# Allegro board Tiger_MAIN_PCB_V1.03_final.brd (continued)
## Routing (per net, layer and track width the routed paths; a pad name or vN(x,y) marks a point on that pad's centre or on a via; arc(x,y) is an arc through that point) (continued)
+V3.3S_AUDIO: length 57.4
  TOP w0.508: v2(20.97,15.87) 20.97,19.72 21.49,20.24 21.49,23.75 v2(20.65,24.59) 19.71,24.59 18.64,25.66 13.33,25.66 10.41,22.74 v2(10.41,21.98) 11.08,21.31 11.08,17.88 10.29,17.09 7.09,17.09 5.77,18.41 5.77,22.44 8.25,24.91 8.25,26.57 v2(7.15,27.67)
  LAY3 w0.305: v2(20.97,15.87) 20.39,15.29 20.39,13.18 17.49,10.28 v2(16.95,10.28)
  BOTTOM w0.203: U16.36 9.67,21.16 C435.2 9.35,21.48 C434.2 10.12,22.27 v2(10.41,21.98)
  BOTTOM w0.305: FB13.1 v2(20.65,24.59) ; R346.1 16.74,10.28 v2(16.95,10.28)
  BOTTOM w0.406: v2(20.97,15.87) 20.97,15.87 R360.2
+V3.3S_MSATA:
  vias: v1(77.27,52.7) v1(78.03,35.61)
+V3P3_BIOS_SPI: length 18.3
  TOP w0.203: R707.1 175.26,51.08 175.02,50.85 175.02,48.48 U42.8 175.26,43.83 174.57,43.14 174.57,40.6 174.09,40.11 174.09,37.75 174.32,37.51 R708.1 174.75,37.05 v2(174.82,36.98) ; R709.1 v2(177.27,36.98)
  BOTTOM w0.203: v2(174.82,36.98) v2(177.27,36.98)
+V3P3A: length 438.1
  TOP w0.203: v2(184.54,48.56) R115.1 R114.1 R113.1 ; 176.66,64.85 176.66,65.68 R632.1 176.22,66.12 R732.2 ; 176.66,64.85 176.61,64.91 175.13,64.91 174.36,64.14 R131.2 ; 176.66,64.85 177.11,64.4 179.96,64.4 R112.2 ; R94.1 v2(187.32,49.75) ; R112.2 R105.2 ; R112.2 181.29,64.41 182.7,64.41 183.65,65.35 R77.1 ; R733.2 183,59.38 v2(182.83,59.21) ; 179.04,73.4 176.58,73.4 176.4,73.57 ; 179.04,73.4 179.04,71.59 179.37,71.26 179.6,71.26 R82.1 180.13,70.68 180.46,70.35 v2(180.46,70.02) 179.78,69.35 R83.1 179.03,68.79 178.16,68.79 177.97,68.98 177.97,69.36 177.81,69.53 176.5,69.53 176.18,69.85 176.18,71.29 176.52,71.63 R56.2 177.65,71.63 R55.2 ; 179.04,73.4 R61.1 R62.1 180.61,73.45 R90.2 181.35,74.48 182.41,75.55 R14.1 183.16,74.98 183.47,74.67 R140.2 ; R113.1 183.86,50.75 R253.1 ; R113.1 R37.1 ; v2(188.56,50.07) 188.55,50.08 R93.2 ; 187.66,82.69 188.25,82.1 R38.1 ; 187.66,82.69 187.65,82.69 187.65,83.09 ; 187.66,82.69 187.25,82.69 ; R134.1 180.39,68.38 v2(180.39,68.33) 179.97,67.91 R57.1 179.98,67.7 R58.1 ; R87.2 v2(179.07,39.09) ; v2(182.93,50.11) 182.9,50.13 R75.1 ; v2(190.11,48.09) R92.1
  TOP w0.254: R523.1 R524.2 244.79,74.82 244.45,75.15 241.64,75.15 241.24,74.76 C282.1 v2(241.8,73.87) U5.1 ; v2(175.54,54.66) 175.54,54.22 R86.1 ; R769.2 v2(163.94,40.93)
  TOP w0.305: LED2.1 103.78,8.47 103.27,8.97 101.25,8.97 99.43,10.79 99.43,14.97 100.89,16.43 100.89,20.65 108.88,28.63 112.22,28.63 v2(113.3,29.71) ; R65.1 R64.1 R63.1 R68.1 188.2,83.63 v2(186.52,81.95) ; v1(168.37,55.01) 167.66,54.3 U6.5 167.52,54.3 R663.2 166.84,53.28 166.39,52.83 166.39,49.5 165.84,48.95 R767.2 165.84,47.74 v2(165.85,47.72) ; v2(173.25,74.93) 173.58,74.93 174.93,73.57 176.4,73.57 ; v2(173.36,64.14) R131.2
  TOP w0.508: v2(173.33,38.69) 173.33,40.37 172.46,41.24 D1.P
  LAY3 w0.203: v2(241.93,42.59) 245.33,39.19 245.33,27.4 248.75,23.99 248.75,16.1 241.23,8.58 169.11,8.58 164.28,13.4 v2(164.28,24.09) ; v2(182.83,59.21) 179.11,59.21 178.21,60.1 176.68,60.1 175.11,58.54 175.11,55.09 v2(175.54,54.66) ; v2(182.93,50.11) 182.49,49.67 182.49,48.78 182.71,48.56 v2(184.54,48.56)
  LAY3 w0.305: v2(180.39,68.33) 180.46,68.4 v2(180.46,70.02) ; v2(173.25,74.93) 173.25,78.25 176.83,81.83 186.4,81.83 v2(186.52,81.95) ; v2(113.3,29.71) 111.57,31.44 111.57,46.88
  LAY3 w0.762: v1(168.56,24.7) 168.56,36.89 167.7,37.75 v2(167.7,38.5) 169.14,39.95 169.14,46.71 168.39,47.46 168.39,49.13 168.83,49.56 168.83,51.11 168.48,51.46 168.48,54.9 v1(168.37,55.01)
  LAY4 w0.305: v2(173.36,64.14) 172.6,63.38 171.54,63.38 170.8,64.12 ; 170.8,64.12 167.75,61.07 167.75,59.86 167.48,59.6 v2(167.04,59.6) ; 170.8,64.12 174.2,67.52 179.58,67.52 v2(180.39,68.33)
  LAY6 w0.203: v2(165.85,47.72) 168.17,47.72 168.64,48.19 170.66,48.19 171.15,47.7 173.09,47.7 173.95,48.56 v2(184.54,48.56) 185.96,49.98 187.09,49.98 v2(187.32,49.75) 188.24,49.75 v2(188.56,50.07) ; v2(173.33,38.69) 178.68,38.69 v2(179.07,39.09)
  LAY6 w0.254: v2(241.93,42.59) 241.8,42.72 v2(241.8,73.87)
  LAY6 w0.508: v2(173.33,38.69) 172.47,39.56 168.75,39.56 v2(167.7,38.5)
  BOTTOM w0.203: v2(175.54,54.66) 174.78,54.66 173.82,53.69 ; v2(190.11,48.09) 190.11,48.18 188.56,49.73 v2(188.56,50.07) ; R544.2 v2(241.93,42.59)
  BOTTOM w0.254: R377.2 138.01,38.75
  BOTTOM w0.305: v2(163.94,40.93) 164.75,40.11 171.91,40.11 v2(173.33,38.69)
  BOTTOM w0.508: v2(167.04,59.6) 167.68,59.6 167.86,59.77
  vias: v1(21.68,61.11) v1(21.68,59.84) v1(22.45,61.11) v1(22.45,59.84) v1(23.21,61.11) v1(23.21,59.84) v1(23.97,61.11) v1(23.97,59.84) v1(111.07,47.38) v1(111.09,48.24) v1(138.87,40.1) v1(162.07,24.81) v1(162.07,24.05)
+V3P3A_DSW: length 393.1
  TOP w0.203: R9.1 190.95,46.86 v2(190.66,46.57)
  TOP w0.508: v1(36.97,54.66) 36.97,55.65 42.19,60.88 43.72,60.88 44.43,61.59 44.43,64.18 45.42,65.17 R23.1 44.62,66.57 44.62,69.05 45.41,69.84 R829.1 45.41,77.04 v2(48.39,80.02)
  LAY3 w0.305: v2(190.66,46.57) 189.6,46.57 189.15,46.11 184.92,46.11 v2(182.42,43.61) ; v2(171.77,43.32) 170.91,44.18 170.91,47.89 170.8,48.01 v2(170.8,52)
  LAY3 w0.508: v2(157.45,53.77) 156.71,54.5 156.71,67.65 155.85,68.51 155.85,70.79 v2(156.44,71.38)
  LAY3 w0.762: v1(148.38,89.89) 146.14,89.89 v1(143.07,92.96)
  LAY3 w1.016: v1(143.07,92.96) 142.69,93.34 106.27,93.34 83.32,70.39 83.32,61.53 76,54.21 74.47,54.21 72.87,52.61 v1(72.87,44.56)
  LAY6 w0.305: v2(171.77,43.32) 172.06,43.61 v2(182.42,43.61) ; v2(157.45,53.77) 159.09,52.13 162.31,52.13 163.23,53.04 169.76,53.04 v2(170.8,52)
  LAY6 w0.508: v2(48.39,80.02) 71.94,80.02 76.65,75.31 v2(85.32,75.31) 87.8,75.31 92.54,70.57 119.66,70.57 123,67.23 142.04,67.23 143.79,68.98 151.55,68.98 153.95,71.38 v2(156.44,71.38)
  LAY6 w1.016: 35.6,50.5 56.85,50.5 62.79,44.56 v1(72.87,44.56)
  BOTTOM w0.203: v2(170.8,52) 170.8,50.4 171.34,49.86 R54.1 172.88,50.8 R19.1 172.91,50.84 R11.1 ; v2(12.22,64.71) 12.06,64.88 12.06,70.24 12.26,70.44 R72.1 ; R18.1 R10.1 191.16,48.12 190.96,47.93 190.96,46.87 v2(190.66,46.57)
  BOTTOM w0.305: R71.1 16.67,61.51 v1(16.13,62.05) ; R132.2 182.42,43.6 v2(182.42,43.61) ; v2(157.45,53.77) 157.95,53.26 R774.1
  BOTTOM w0.508: v2(85.32,75.31) 85.32,77.61 86.03,78.31 D30.P ; v2(14.7,65.87) 14.69,65.88 R776.2
  BOTTOM w0.762: v1(148.38,89.89) 150.22,88.04 150.22,79.78 149.65,79.21 FB45.2
  vias: v1(13.86,62.42) v1(14.62,62.42) v1(15.39,62.42) v1(36.11,54.66)
+V3P3A_RTC: length 156.9
  TOP w0.178: U1.BB14 194.51,54.29 v2(194.52,54.27)
  TOP w0.254: U1.AK19 v2(197.87,61.42)
  LAY3 w0.305: v2(182.26,42.07) 177.6,42.07 175.84,43.84 175.84,45.74 176.71,46.61 176.75,46.61 ; v2(174.3,47.91) 175.62,47.91 176.75,46.79 176.75,46.61 ; 176.75,46.61 v2(177.17,46.61)
  LAY3 w0.508: v2(85.97,56.43) 85.97,68.16 89.4,71.59 v2(89.4,74.84)
  LAY6 w0.508: v2(85.97,56.43) 86.53,56.99 91.56,56.99 92.28,56.27 95.81,56.27 97.86,54.22 100.31,54.22 101.3,55.22 113.28,55.22 117.96,50.53 140.01,50.53 145.34,45.19 156.86,45.19 157.73,46.06 158.6,46.06 159.73,47.19 163.87,47.19 164.34,46.72 173.11,46.72 v2(174.3,47.91)
  BOTTOM w0.152: v2(174.3,47.91) 174.3,49.09 173.72,49.68 R12.2
  BOTTOM w0.203: v2(177.17,46.61) R6.2 R7.2
  BOTTOM w0.254: 193.34,49.65 193.15,49.46 193.15,43.77 190.84,41.46 182.87,41.46 v2(182.26,42.07)
  BOTTOM w0.508: v2(89.4,74.84) 89.4,75.34 88.93,75.81 D31.N D30.N
+V3P3A_SIP: length 129.5
  TOP w0.254: U1.AG15 194.71,63.56 v2(194.97,63.21) ; U1.AK17 v2(196.05,61.42) ; U1.Y16 v2(195.62,66.57) ; v2(194.22,61.42) 194.27,61.48 U1.AK15 194.97,62.27 v2(194.97,62.38) ; U1.V19 v2(197.58,67.4) ; U1.AJ21 v2(198.88,63.21) ; U1.T16 v2(195.62,68.24)
  TOP w0.305: v2(194.97,62.38) 195.3,62.71 U1.AJ16 ; C225.2 178.42,61.74 v2(178.4,61.72)
  LAY3 w0.152: 187.62,62.2 188.47,63.05 194.79,63.05 194.95,63.21 v2(194.97,63.21)
  LAY3 w0.254: v2(178.4,61.72) 178.89,62.2 187.62,62.2
  LAY4 w0.254: v2(172.09,64.11) 172.09,64.61 174.34,66.86 181.72,66.86 182.22,67.36 194.73,67.36 v2(195.62,68.24) ; v2(195.62,66.57) 195.62,66.28 195.36,66.02 194.35,66.02 193.66,65.34 178.1,65.34 177.09,64.33 174.67,64.33 172.57,62.23 v2(172.09,62.23)
  BOTTOM w0.254: v2(172.09,64.11) C229.2 170.7,63.31 R119.2 ; R127.2 191.38,36.59 197.76,42.97 197.76,51.37 C245.2 ; 169.41,62.07 169.65,62.31 170.93,62.31 C226.2 171.64,61.79 v2(172.09,62.23)
  BOTTOM w0.508: 177.12,41.66 177.12,39.75 181.18,35.69 184.84,35.69 185.21,36.06 R127.2 ; 168.52,51.72 173.18,47.06 175.4,47.06 175.4,43.38 ; R119.2 170.7,63.07 169.39,63.07
  vias: v2(184.09,55.43) v2(184.65,55.43)
+V5_AVDD: length 4.4
  BOTTOM w0.203: 10.91,16.83 11.24,17.16 U16.26
  BOTTOM w0.406: 9.06,14.82 10.42,14.82 10.91,15.31 10.91,16.83
+V5_PVDD: length 12.4
  BOTTOM w0.203: 16.52,23.4 16.52,22.77 15.93,22.19 U16.46 ; U16.41 13.93,22.58 13.09,23.42 13.09,23.64
  BOTTOM w0.508: 16.52,23.4 16.27,23.64 16.27,24.68 16.15,24.81 C449.2 16.15,25.7 C450.1 13.52,26.36 ; C448.1 13.09,25.94 C447.2 12.83,24.94 12.83,23.9 13.09,23.64
+V5A: length 504.4
  TOP w0.203: R563.1 41.1,22.45 41.61,21.94 41.61,21.08 41.25,20.73 41.25,19.52 ; R558.1 60.96,12.18
  TOP w0.254: v2(170.98,79.26) 171.01,79.29 C807.2 171.16,79.82 171.95,80.62 U56.4 ; U67.4 167.91,61.09 C689.2 167.25,61.09 166.88,61.46 v2(166.88,62.72) ; C758.2 160.66,46.48 160.66,46.26 161.04,45.88 U41.10
  TOP w0.305: v2(156.66,43.71) 156.66,42.63 158.36,40.93 162.62,40.93 163.72,39.82 165.08,39.82 ; v2(156.66,43.71) D26.P 153.08,43.71 152.79,44 v1(151.85,44) ; v2(156.66,43.71) 157.19,44.24 157.19,45.44 158.04,46.29 159.65,46.29 C758.2 ; 165.08,39.82 165.07,39.82 v2(165.07,38.03) 167.02,36.08 173.25,36.08 v2(173.39,36.22) ; 165.08,39.82 165.59,39.82 168.76,43 168.76,43.88 R763.2 ; v2(240.14,83.42) 240.28,83.28 246.96,83.28 250.53,86.85 v2(250.53,90)
  TOP w0.508: 18.31,70.44 18.31,72.14 v2(16.62,73.83)
  LAY3 w0.203: v2(165.07,38.03) 165.07,27.87 165.85,27.08 165.85,18.08 173.7,10.23 176.66,10.23 177.68,9.22 240.97,9.22 248.07,16.32 248.07,23.34 244.7,26.72 244.7,35.8 241.59,38.9 v2(241.59,39.95)
  LAY3 w0.305: v2(156.66,43.71) 157.12,44.17 157.12,48.45 158.04,49.37 158.04,55.24 157.31,55.98 157.31,62.81 v2(157.36,62.86) ; v2(173.39,36.22) 173.39,30.63 v2(174.46,29.56) 174.56,29.56 v2(176.26,27.86)
  LAY3 w0.406: v2(204.78,97.48) 205.17,97.87 207.07,97.87 208.39,99.2 218.08,99.2 219.12,100.24 237.17,100.24 239.98,103.06 247.08,103.06 250.53,99.61 v2(250.53,90)
  LAY3 w0.508: v2(204.78,97.48) 184.83,97.48 184.3,96.95 181.17,96.95 180.15,97.97 176.21,97.97 175.87,97.64 170.89,97.64 169.18,95.93 v2(169.18,95.71)
  LAY3 w1.016: v1(151.85,44) 150.89,44.95 143.88,44.95 132.38,56.46 v1(124.06,56.46)
  LAY6 w0.305: v2(166.88,62.72) 166.58,63.03 162.16,63.03 161.57,63.61 157.79,63.61 157.36,63.18 v2(157.36,62.86) ; v2(241.59,39.95) 240.88,40.66 v2(240.88,42.11) 240.88,45.58 239.32,47.14 238.36,47.14 v2(236.96,48.54) 236.96,51.37 241.13,55.54 241.13,74.14 239.5,75.78 239.5,82.79 v2(240.14,83.42)
  LAY6 w0.406: v2(250.53,90) 250.32,90.2 243.76,90.2 243.24,89.68 236.24,89.68 235.1,90.82 v2(235.1,91.2)
  BOTTOM w0.152: v2(236.96,48.54) 237.32,48.89 R813.2
  BOTTOM w0.203: U103.34 238.57,85.05 C716.2 239.08,84.23 239.88,83.42 v2(240.14,83.42) ; R270.2 v2(174.46,29.56) ; 240.7,38.17 U29.9 ; U71.14 16.36,73.34 16.62,73.59 v2(16.62,73.83)
  BOTTOM w0.254: U45.6 176.76,95.47 C321.1 ; v2(204.78,97.48) 204.78,96.73 205.4,96.11 C323.1 207.76,96.32 U50.6 ; v2(170.98,79.26) 170.98,80.98 165.88,86.08 163.72,86.08 ; U59.4 157.01,61.48 C702.2 157.01,62.51 v2(157.36,62.86)
  BOTTOM w0.305: v2(176.26,27.86) C512.1 176.66,26.94 U21.6 ; 165.88,86.08 165.88,93.92 167.67,95.71 v2(169.18,95.71) 170.44,94.45 175.73,94.45 C321.1 ; R553.1 v2(240.88,42.11) ; 163.72,86.08 158.74,86.08 C325.1 158.74,87.75 159.23,88.24 U54.6 ; 240.7,38.17 241.44,38.92 C696.2 ; R814.2 v1(30.26,71.93)
  BOTTOM w0.406: v2(241.59,39.95) C696.2 ; v1(29.5,71.93) 27.12,71.93 26.64,71.45 C778.1 26.64,70.99 D24.1
  BOTTOM w0.508: v2(19.56,65.59) 19.91,65.94 R782.1
  vias: v1(26.5,42.31) v1(26.88,88.3) v1(27.26,42.31) v1(27.64,88.3) v1(28.03,42.31) v1(29.5,71.17) v1(29.5,70.4) v1(30.26,71.17) v1(30.26,70.4) v1(36.64,45.79) v1(41.23,16.09) v1(61.22,11.11)
+V5S: length 331.6
  TOP w0.152: R625.2 191.29,40.57 190.48,39.76 188.63,39.76 188.31,39.44 188.31,35.92 178.24,25.85 171.07,25.85 v2(170.64,26.28)
  TOP w0.203: R608.1 v2(161.4,12.89)
  TOP w0.406: R535.2 137.36,55.72 v2(136.44,56.64) 136.44,57.48 137.38,58.42 144.9,58.42 145.77,57.55 C564.1 U35.6
  TOP w0.508: R817.2 36.39,75.28 33.95,75.28 33.11,76.12 33.11,77.07 ; FB21.2 162.85,22.5 163.34,22.98 v2(164.81,22.98)
  LAY3 w0.203: v2(164.81,22.98) 164.81,13.94 v2(165.86,12.89) 169.87,8.89 241.1,8.89 248.38,16.16 248.38,23.69 245.03,27.05 245.03,35.91 242.14,38.79 242.14,40.05 238.32,43.87 v2(238.32,44.6)
  LAY3 w0.406: v2(136.44,56.64) 135.57,57.51 122.87,57.51 v1(121.9,56.55)
  LAY3 w0.508: v1(121.9,56.55) 121.9,56 122.38,55.52 131.72,55.52 148.96,38.27 153.36,38.27 165.04,26.59 165.04,23.21 v2(164.81,22.98)
  LAY3 w1.016: v1(5.23,14.42) 4.22,15.43 4.22,27.43 8.5,31.71 v1(12.41,31.71)
  LAY6 w0.203: v2(164.81,22.98) 165.71,22.98 169.02,26.28 v2(170.64,26.28) ; v1(30.32,80.34) v2(30.32,86.97)
  LAY6 w0.508: v2(43.11,67.36) 39.59,67.36 35.06,71.88 34.03,71.88 32.91,73.01 32.91,78 v1(31.84,79.07)
  BOTTOM w0.203: R152.1 v2(238.32,44.6) ; R342.1 26.52,89.28 28.62,89.28 30.32,87.58 v2(30.32,86.97) ; v2(161.4,12.89) v2(165.86,12.89)
  BOTTOM w0.254: R399.1 R404.1 R400.1 v2(43.11,67.36)
  vias: v1(12.41,30.95) v1(23.64,50.89) v1(23.64,49.84) v1(24.4,50.89) v1(24.4,49.84) v1(29.56,80.34) v1(29.56,79.07) v1(30.32,79.07) v1(31.08,80.34) v1(31.08,79.07) v1(31.84,80.34)
+V5S_HDD:
  vias: v1(98.41,54.95) v1(99.3,54.97)
+V15A: length 6.8
  TOP w0.406: R70.1 v2(23.21,63.46)
  BOTTOM w0.305: v2(23.21,63.46) 24.28,62.4 25.13,62.4 R809.1 25.14,61.26 R806.1
  BOTTOM w0.406: v2(23.21,63.46) 22.99,63.46 D25.2 22.37,63.51 C776.1
+VCCCORE: length 148.2
  TOP w0.102: 211.11,72.01 211.13,72.04 U1.K43
  TOP w0.127: 205.65,72.22 U1.K33 ; U1.K33 205.93,72.5 ; U1.K33 205.65,72.78 ; 207.02,61.94 U1.AL37 ; U1.AL37 207.02,61.39 ; U1.AL37 206.74,61.66 ; U1.AL37 207.3,61.66 ; U1.J37 208.21,72.97 ; U1.J37 207.65,72.97 ; U1.J37 207.93,72.69 ; U1.J37 207.93,73.24 ; U1.AK33 205.65,62.41 ; U1.AK33 205.65,61.85 ; U1.AK33 205.37,62.13 ; U1.AK37 207.2,62.13 ; U1.AK37 207.48,61.85 ; U1.AK37 207.48,62.41 ; U1.AM33 205.93,61.19 ; U1.AM33 205.65,60.91 ; U1.AM33 205.37,61.19 ; U1.AM33 205.65,61.47 ; 208.85,61.94 U1.AL40 ; U1.AL40 209.13,61.66 ; U1.AL40 208.57,61.66 ; U1.AL40 208.85,61.39 ; U1.G38 v2(207.93,73.68) U1.G37 ; U1.G37 207.48,73.15 ; U1.G37 207.76,73.43 ; U1.K40 209.58,72.5 ; U1.K40 209.3,72.22 ; U1.K40 209.3,72.78 ; 209.3,61.85 U1.AK40 ; U1.AK40 209.3,62.41 ; U1.AK40 209.03,62.13 ; U1.AK40 209.58,62.13 ; 207.48,60.91 U1.AM37 ; U1.AM37 207.2,61.19 ; U1.AM37 207.76,61.19 ; U1.AM37 207.48,61.47 ; U1.G33 v2(206.1,73.68) U1.G35 ; U1.G33 205.65,73.15 ; U1.G33 205.88,73.18 ; U1.AM38 208.11,61.19 ; U1.AM38 208.39,60.91 ; U1.AM38 208.67,61.19 ; U1.AM38 208.39,61.47 ; U1.AK38 208.67,62.13 ; U1.AK38 208.39,61.85 ; U1.AK38 208.39,62.41 ; U1.J33 205.82,72.97 ; U1.J33 206.38,72.97 ; U1.J33 206.1,72.69 ; U1.J33 206.1,73.24 ; U1.AL33 204.91,61.66 ; U1.AL33 205.47,61.66 ; U1.AL33 205.19,61.39 ; U1.AL33 205.19,61.94 ; U1.K37 207.48,72.78 ; U1.K37 207.48,72.22 ; U1.K37 207.76,72.5 ; 206.56,61.47 U1.AM35 ; U1.AM35 206.28,61.19 ; U1.AM35 206.56,60.91 ; U1.AM35 206.84,61.19 ; v2(204.28,73.68) U1.G32 204.73,73.15 ; U1.K38 208.11,72.5 ; U1.K38 208.39,72.22 ; U1.K38 208.39,72.78 ; U1.J30 204.28,73.24 ; U1.J30 204.28,72.69 ; U1.J30 204.55,72.97 ; 204.73,61.5 U1.AM32 204.73,60.89 ; U1.J40 209.48,72.97 ; U1.J40 209.76,72.69 ; U1.J40 210.04,72.97 ; U1.J40 209.76,73.24 ; U1.K35 206.28,72.5 ; U1.K35 206.56,72.78 ; U1.K35 206.56,72.22 ; 206.57,73.03 U1.G35 ; U1.G35 206.28,73.43 ; U1.G35 206.56,73.15 ; U1.K42 210.22,72.22 ; U1.K42 210.22,72.78 ; U1.K42 v2(209.76,72.27) ; U1.AK35 206.56,62.41 ; U1.AK35 206.56,61.85 ; U1.AK35 206.84,62.13
  TOP w0.152: 208.39,73.07 U1.G38 ; 209.3,73.09 U1.G40 209.51,73.43 v2(209.76,73.68) 210.02,73.43 U1.G42 210.22,73.1
  TOP w0.203: U1.G30 v2(204.28,73.68) ; U1.A39 v2(209.2,78.04) ; U1.A34 v2(206.72,78.04) ; U1.A30 v2(204.24,78.14) ; U1.A44 v2(211.68,78.04)
  TOP w0.305: v2(187.84,86.1) 187.83,86.08 R815.2 ; C34.2 204.75,78.94 204.24,78.43 v2(204.24,78.14) ; C32.2 206.1,78.27 206.34,78.04 v2(206.72,78.04) ; v2(209.2,78.04) 208.58,78.66 C33.2
  LAY6 w0.254: v2(197,100.33) 197.11,100.44 209.94,100.44 211.16,101.66 232.56,101.66 234.31,103.41 242.27,103.41 244.11,101.57 244.66,101.57 v2(245.19,102.1)
  LAY6 w0.305: v2(241.33,100.12) 240.04,100.12 237.42,102.74 v2(235.76,102.74)
  BOTTOM w0.203: C304.1 243.16,96.92 C303.2 ; C304.1 243.16,96.43 243.42,96.18 243.42,95.68 R217.1 ; C304.1 243.89,97.65 C307.1 244.07,98.14 R244.1 ; 210.54,64.52 210.75,64.31 210.75,63.69 210.53,63.47 C62.1 C50.1 ; R214.2 243.47,100.4 R215.1 245.19,101.3 v2(245.19,102.1)
  BOTTOM w0.254: R244.1 245.28,99.42 R215.1
  BOTTOM w0.305: v2(241.33,100.12) 241.65,100.44 241.65,101.2 R681.2 ; v2(235.76,102.74) 226.03,102.74 224.41,101.13 224.41,97.16 223.33,96.08 223.33,93.12 222.32,92.11 219.94,92.11 219.18,91.35 216.88,91.35 214.4,88.87 214.4,87.87
  vias: v1(192.41,93.51) v1(193.19,93.51) v1(193.87,90.92) v1(194.5,93.51) v1(194.65,90.92) v1(195.24,93.51) v1(195.96,93.51) v1(195.91,90.88) v1(195.96,90.05) v1(196.75,93.51) v1(196.7,90.88) v1(197.79,90.83) v1(197.8,90.01) v1(198.07,93.51) v1(198.58,90.83) v1(198.51,88.79) v1(198.59,90.01) v1(198.81,93.51) v1(199.26,88.79) v1(199.33,89.98) v1(199.56,93.51) v1(199.89,86.41) v1(200.34,93.51) v1(202.82,90.72) v1(203.38,90.21) v1(203.96,89.73) v2(192.49,85.59) v2(194.3,85.58) v2(200.26,85.2) v2(200.26,84.63) v2(200.23,82.97) v2(200.78,82.44) v2(202.29,91.65) v2(202.96,82.13) v2(203.01,79.32) v2(203.92,82.2) v2(204.28,72.27) v2(204.59,68.41) v2(204.59,67.33) v2(204.59,66.26) v2(205.19,62.36) v2(205.39,71.57) v2(205.65,63.07) v2(206.1,72.27) v2(206.1,60.8) v2(206.39,71.56) v2(206.56,63.07) v2(207.02,62.36) v2(207.02,60.8) v2(207.16,68.37) v2(207.16,67.29) v2(207.16,66.22) v2(207.48,71.56) v2(207.48,63.07) v2(207.71,68.37) v2(207.71,67.29) v2(207.71,66.22) v2(207.93,72.27) v2(207.93,60.8) v2(208.26,71.56) v2(208.39,63.07) v2(208.85,62.36) v2(209.43,71.56) v2(210.12,71.56) v2(210.35,80.03) v2(210.35,78.13) v2(210.35,68.39) v2(210.35,67.32) v2(210.35,66.24)
+VCCDSW_1P0: length 2.4
  TOP w0.152: 185.79,61.35 U1.AL1
  TOP w0.305: 185.79,61.35 185.77,61.37 C228.1
+VCCGT: length 116.9
  TOP w0.076: 217.99,73.27 U1.J55 217.99,72.66 ; U1.K60 220.28,72.19 ; U1.K60 220.58,72.5 ; U1.K60 219.97,72.5 ; U1.K60 220.28,72.81 ; 214.03,72.97 U1.J48 ; U1.J48 214.33,73.27 ; U1.J48 214.33,72.66 ; 213.57,72.5 U1.K48 ; U1.K48 213.88,72.81 ; U1.K48 213.88,72.19 ; U1.K48 214.18,72.5 ; 217.23,72.5 U1.K55 ; U1.K55 217.53,72.19 ; U1.K55 217.53,72.81 ; U1.K55 217.84,72.5 ; 218.91,72.66 U1.J56 218.91,73.27 ; 219.67,72.5 U1.K58 ; U1.K58 219.36,72.81 ; U1.K58 219.36,72.19 ; U1.K58 219.06,72.5 ; 216.31,72.5 U1.K53 ; U1.K53 216.62,72.81 ; U1.K53 216.62,72.19 ; U1.K53 216.93,72.5 ; U1.J53 217.38,72.97 ; U1.J53 217.08,72.66 ; U1.J53 216.77,72.97 ; U1.L67 224.25,71.31 ; U1.L67 224.56,71.61 ; U1.L67 224.86,71.31 ; 213.11,72.97 U1.J46 213.42,72.66 ; U1.K50 214.79,72.19 ; U1.K50 214.49,72.5 ; U1.K50 215.1,72.5 ; U1.K50 214.79,72.81 ; 215.55,72.97 U1.J50 215.25,72.66 ; 225.51,65.82 U1.AC68 225.21,66.13 ; 226.16,71.31 U1.L69 225.55,71.31 ; U1.K52 215.71,72.81 ; U1.K52 215.4,72.5 ; U1.K52 216.01,72.5 ; U1.K52 215.71,72.19 ; 211.9,72.97 U1.J43 211.93,73.12 ; U1.J45 212.51,73.27 ; U1.J45 212.51,72.66 ; U1.J45 212.81,72.97 ; U1.K56 218.45,72.19 ; U1.K56 218.75,72.5 ; U1.K56 218.14,72.5 ; U1.K56 218.45,72.81 ; 219.82,72.66 U1.J58 219.55,72.7 ; 227.46,71.31 U1.L71 226.85,71.31 ; 216.16,73.27 U1.J52 216.16,72.66 ; 224.21,71.31 U1.L66 223.6,71.31 ; U1.J60 220.73,73.27 ; U1.L65 223.25,71.61
  TOP w0.102: 224.52,69.75 224.56,69.72 U1.R67 ; U1.R68 225.21,69.17 ; U1.R68 224.9,69.48 ; U1.R68 225.21,69.7 225.25,69.74 ; U1.R68 225.51,69.48 ; U1.W66 223.91,67.9 223.88,67.93 ; U1.W66 223.91,67.34 ; U1.W66 223.6,67.65 ; U1.W66 224.21,67.65 ; U1.M62 221.49,70.54 ; U1.M62 221.79,70.85 ; U1.M62 221.18,70.85 ; U1.M62 221.49,71.15 ; U1.AA64 222.6,66.48 222.58,66.45 ; U1.AA64 222.6,67.04 ; U1.AA64 222.3,66.73 ; 222.26,70.39 U1.N63 ; U1.N63 221.65,70.39 ; U1.N63 221.95,70.7 ; U1.N63 221.95,70.09 ; U1.L64 222.6,71.61 ; U1.L64 222.3,71.31 ; U1.L64 222.91,71.31 ; U1.L64 222.6,71 ; U1.L63 221.95,71 ; U1.L63 222.26,71.31 ; U1.L63 221.95,71.61 ; U1.L63 221.65,71.31 ; 221.65,66.73 U1.AA63 ; U1.AA63 221.95,67.04 ; U1.AA63 221.95,66.43 ; U1.AA63 222.26,66.73 ; 223.56,68.56 U1.U65 ; U1.U65 222.95,68.56 ; U1.U65 223.25,68.26 ; U1.U65 223.25,68.87 ; 224.54,66.45 224.55,66.46 224.55,66.73 U1.AA67 ; U1.W64 222.6,67.34 ; U1.W64 222.3,67.65 ; U1.W64 222.6,67.9 222.63,67.93 ; U1.W64 222.91,67.65 ; v2(224.23,66.28) U1.AA67 ; U1.AA67 224.86,66.73 ; U1.AA67 224.25,66.73 ; U1.AA67 224.56,67.04 ; U1.N70 226.51,70.09 ; U1.N70 226.51,70.7 ; U1.N70 226.2,70.39 ; U1.N70 226.81,70.39 ; U1.AA69 225.86,66.43 ; U1.AA69 225.55,66.73 ; U1.AA69 225.86,67.04 ; U1.AA69 226.16,66.73 ; 222.26,69.48 U1.R63 ; U1.R63 221.95,69.17 ; U1.R63 221.95,69.78 ; U1.R63 221.65,69.48 ; U1.AC69 225.86,66.13 ; U1.AC69 225.55,65.82 ; U1.AC69 226.16,65.82 ; 225.51,71.31 U1.L68 ; U1.L68 224.9,71.31 ; U1.L68 225.21,71.61 ; U1.L68 225.21,71 ; U1.AC70 226.51,66.13 ; U1.AC70 226.2,65.82 ; U1.AC70 U1.AC71 ; U1.AC70 226.51,65.59 226.6,65.5 ; 222.57,70.12 222.6,70.16 U1.N64 ; 226.53,67.93 226.51,67.9 U1.W70 ; 222.3,69.48 U1.R64 ; U1.R64 222.6,69.71 222.57,69.75 ; U1.R64 222.91,69.48 ; U1.R64 222.6,69.17 ; 225.51,67.65 U1.W68 ; U1.W68 225.21,67.34 ; U1.W68 225.21,67.95 ; U1.W68 224.9,67.65 ; U1.U68 225.21,68.87 ; U1.U68 v2(224.88,68.11) ; U1.U68 225.21,68.26 ; U1.U68 225.51,68.56 ; U1.U68 224.9,68.56 ; U1.L62 221.49,71.46 ; U1.L62 221.18,71.76 ; U1.L62 221.79,71.76 ; U1.L62 221.49,72.07 ; U1.AC64 222.6,66.05 222.57,66.09 ; U1.AC64 U1.AC65 ; U1.AC64 222.6,65.51 ; U1.AC64 222.3,65.82 ; U1.N69 225.86,70.09 ; U1.N69 226.16,70.39 ; U1.N69 225.55,70.39 ; U1.N69 225.86,70.7 ; 224.21,65.82 U1.AC66 ; U1.AC66 223.6,65.82 ; U1.AC66 223.91,66.13 ; 221.9,67.94 221.95,67.88 U1.W63 ; U1.Y62 221.49,66.89 ; U1.Y62 221.49,67.5 ; U1.Y62 221.79,67.19 ; U1.Y62 221.18,67.19 ; 225.55,67.65 U1.W69 ; U1.W69 225.86,67.86 225.81,67.9 ; U1.W69 225.86,67.34 ; U1.W69 226.16,67.65 ; 223.56,69.48 U1.R65 ; U1.R65 222.95,69.48 ; U1.R65 223.25,69.73 223.28,69.76 ; U1.R65 223.25,69.17 ; U1.AC65 223.25,66.08 223.28,66.1 ; U1.AC65 223.56,65.82 ; 226.85,68.56 U1.U71 ; U1.U71 227.16,68.87 ; U1.U71 227.46,68.56 ; U1.U71 227.16,68.26 ; U1.L70 226.51,71.61 ; U1.L70 226.51,71 ; U1.L70 226.2,71.31 ; U1.L70 226.81,71.31 ; U1.N71 227.16,70.09 ; U1.N71 227.16,70.7 ; U1.N71 227.46,70.39 ; U1.N71 226.85,70.39 ; 227.46,66.73 U1.AA71 ; U1.AA71 227.16,66.43 ; U1.AA71 227.16,67.04 ; U1.AA71 226.85,66.73 ; U1.R69 225.86,69.78 ; U1.R69 226.16,69.48 ; U1.R69 225.55,69.48 ; U1.R69 225.86,69.17 ; U1.N66 223.91,70.09 ; U1.N66 223.91,70.7 ; U1.N66 224.21,70.39 ; U1.N66 223.6,70.39 ; 226.2,66.73 U1.AA70 ; U1.AA70 226.81,66.73 ; U1.AA70 226.51,67.04 ; U1.AA70 226.51,66.43 ; U1.AC71 227.16,65.54 ; U1.AC71 227.16,66.13 ; U1.R71 227.16,69.78 ; U1.R71 226.85,69.48 ; U1.R71 227.46,69.48 ; U1.R71 227.16,69.17 ; 224.57,67.93 224.56,67.91 U1.W67 ; U1.L66 223.91,71 ; U1.W70 226.51,67.34 ; U1.W70 226.2,67.65 ; U1.W70 226.81,67.65 ; U1.N67 224.25,70.39 ; U1.N67 224.56,70.7 ; U1.N67 224.56,70.17 224.51,70.13 ; 223.6,66.73 U1.AA66 ; U1.AA66 223.91,67.04 ; U1.AA66 224.21,66.73 ; U1.AA66 223.91,66.43 ; 221.65,67.65 U1.W63 ; U1.W63 222.26,67.65 ; U1.W63 221.95,67.34 ; 226.2,69.48 U1.R70 ; U1.R70 226.51,69.17 ; U1.R70 226.81,69.48 ; U1.R70 226.51,69.78 ; 223.56,71.31 U1.L65 ; U1.L65 222.95,71.31 ; U1.L65 223.25,71 ; 223.6,69.48 U1.R66 ; U1.R66 223.91,69.78 ; U1.R66 224.21,69.48 ; U1.R66 223.91,69.17 ; 224.56,71 U1.L67 ; U1.N64 222.3,70.39 ; U1.N64 222.6,70.7 ; 227.46,67.65 U1.W71 ; U1.W71 226.85,67.65 ; U1.W71 227.16,67.34 ; U1.W71 227.16,67.95 ; U1.R67 224.86,69.48 ; U1.R67 224.56,69.17 ; U1.R67 224.25,69.48 ; U1.L71 227.16,71 ; 224.52,66.09 224.56,66.06 U1.AC67 ; U1.T62 221.49,69.33 ; U1.T62 221.18,69.02 ; U1.T62 221.49,68.71 ; U1.T62 221.79,69.02 ; 223.25,67.34 U1.W65 ; U1.W65 223.25,67.95 ; U1.W65 223.45,67.37 v2(223.58,67.19) ; U1.W65 223.56,67.65 ; U1.W65 222.95,67.65 ; U1.L69 225.86,71 ; U1.AC67 224.25,65.82 ; U1.AC67 U1.AC68 ; 224.25,67.65 U1.W67 ; U1.W67 224.86,67.65 ; U1.W67 224.56,67.34 ; 226.83,65.76 226.83,65.53
  TOP w0.127: 227.5,71.31 U1.L71 226.85,71.31 ; 220.11,72.97 U1.J58 ; U1.J58 219.52,72.97 ; U1.J58 219.82,72.66 ; 214.67,72.97 U1.J48 ; U1.J48 214.33,72.67 ; U1.J48 214.04,72.95 ; U1.J50 215.24,72.66 ; U1.J50 214.91,72.97 ; U1.J50 215.55,72.98 ; U1.J55 217.68,72.97 ; U1.J55 217.99,72.65 ; U1.J55 218.32,72.97 ; U1.J45 212.5,72.67 ; U1.J45 212.21,72.97 ; U1.J45 212.81,72.98 ; 211.84,73.16 U1.J43 ; U1.J43 211.88,72.85 ; U1.J43 211.59,72.65 ; U1.J60 221.03,72.97 ; U1.J60 220.72,72.69 ; U1.J60 220.44,72.97 ; U1.J52 216.46,72.97 ; U1.J52 215.87,72.97 ; U1.J52 216.15,72.65 ; U1.J56 219.23,72.97 ; U1.J56 218.57,72.97 ; U1.J56 218.9,72.67 ; 226.19,71.31 U1.L69 225.51,71.3 ; 224.88,71.31 U1.L67 224.27,71.29 ; U1.J46 213.41,72.65 ; U1.J46 213.07,72.98 ; U1.J46 213.8,72.97 ; 223.16,71.63 U1.L65 ; U1.J53 217.07,72.66 ; U1.J53 216.77,72.98 ; U1.J53 217.45,72.95 ; 223.6,71.3 U1.L66 224.21,71.3
  TOP w0.203: v2(214.1,78.14) 214.16,78.09 U1.A48 ; U1.A58 v2(219.11,78.14) ; U1.A53 v2(216.63,78.14) ; U1.A62 v2(221.59,78.14) ; U1.A66 v2(224.07,78.14)
  TOP w0.305: C87.1 233.33,69.5 ; 233.31,70.1 232.79,70.1 ; 231.79,70.1 231.19,70.1 ; 231.81,69.5 231.81,70.1 ; 233.36,70.1 233.87,70.1
  LAY6 w0.305: v2(216.63,78.14) v2(214.1,78.14)
  BOTTOM w0.305: C296.1 231.58,97.49 230.51,97.49 R204.2 ; C296.1 233.26,96.98 233.62,96.62 C294.1 ; C296.1 R206.1 232.09,98.74 v2(232.07,98.75)
  BOTTOM w0.406: C294.1 C297.1 R207.2 R212.2
  vias: v1(217.29,88.77) v1(217.29,88.01) v1(217.47,90.58) v1(218.23,90.58) v1(218.58,88.77) v1(218.58,88.01) v1(219.02,90.58) v1(219.78,90.58) v1(219.8,88.77) v1(219.8,88.01) v1(220.87,91.16) v1(221.64,91.16) v1(222.42,91.16) v1(223.19,91.16) v1(225.12,91.16) v1(225.88,91.16) v1(226.67,91.16) v1(227.43,91.16) v1(228.61,90.55) v1(228.75,67.76) v1(228.83,88.74) v1(228.83,87.97) v1(229.37,90.54) v1(229.54,88.74) v1(229.54,87.97) v1(230.13,90.54) v1(230.25,88.74) v1(230.25,87.97) v1(233.47,101.53) v1(234.26,101.53) v1(235.01,101.53) v1(235.79,101.53) v2(210.71,62.54) v2(211.13,63.07) v2(211.61,72.16) v2(212.05,71.56) v2(212.05,63.07) v2(212.51,72.27) v2(212.51,62.36) v2(212.96,71.56) v2(212.96,63.07) v2(213.42,72.27) v2(213.88,71.56) v2(213.88,63.07) v2(214.33,72.27) v2(214.33,62.36) v2(214.33,60.8) v2(214.79,71.56) v2(214.79,63.07) v2(215.25,72.27) v2(215.25,60.8) v2(215.71,71.56) v2(215.71,63.07) v2(216.16,72.27) v2(216.16,62.36) v2(216.17,60.84) v2(216.62,71.56) v2(216.62,63.07) v2(217.08,72.27) v2(217.08,60.8) v2(217.53,71.56) v2(217.53,63.07) v2(217.99,72.27) v2(217.99,62.36) v2(218.45,71.56) v2(218.45,63.07) v2(218.91,72.27) v2(218.97,60.84) v2(219.24,63.07) v2(219.36,71.56) v2(219.82,72.27) v2(219.82,60.8) v2(220.28,71.56) v2(220.42,81.41) v2(220.66,72.27) v2(220.72,88.88) v2(221.07,71.28) v2(221.26,90.44) v2(221.77,90.45) v2(222.28,69.02) v2(222.28,67.19) v2(222.93,68.11) v2(223.58,70.85) v2(223.58,69.02) v2(223.85,93.29) v2(224.23,69.93) v2(224.31,93.29) v2(224.77,93.29) v2(224.88,70.85) v2(224.88,69.02) v2(224.88,67.19) v2(225.22,93.29) v2(225.53,69.93) v2(225.53,66.28) v2(226.18,70.85) v2(226.18,69.02) v2(226.18,67.19) v2(226.64,93.29) v2(226.83,69.93) v2(226.83,68.11) v2(226.83,66.28) v2(227.1,93.29) v2(227.56,93.29) v2(228.02,93.29) v2(229.15,93.29) v2(229.6,93.29) v2(229.85,91.18) v2(230.06,93.29) v2(230.38,91.19) v2(230.52,93.29) v2(230.67,70.1) v2(230.67,68.07) v2(234.17,72.64) v2(234.22,70.1) v2(234.22,68.07) v2(234.88,72.64) v2(236.28,68.48) v2(236.53,72.67) v2(236.99,68.48) v2(237.25,72.67)
+VCCPAZIO: length 33.8
  TOP w0.203: v2(189.63,40.22) 189.77,40.36 R799.1
  TOP w0.254: U1.AJ19 v2(197.58,62.38)
  TOP w0.305: R796.1 193.64,38.58 v2(189.63,38.58)
  BOTTOM w0.406: R127.1 185.21,38.09 189.14,38.09 v2(189.63,38.58) v2(189.63,40.22) 192.28,40.22 197.13,45.07 197.13,51.82 C244.2 ; R127.1 185.19,38.11 R826.1 ; R127.1 R126.1
+VCCPDSW_3P3: length 1.6
  TOP w0.254: U1.AD18 196.33,64.97 v2(196.27,64.89) U1.AD17 ; U1.AJ17 v2(196.28,62.38)
+VCCPGPPD: length 26.1
  TOP w0.254: U1.Y15 v2(194.32,66.57)
  LAY4 w0.254: v2(194.32,66.57) 194.07,66.57 193.89,66.38 188.81,66.38 188.19,65.75 177.86,65.75 176.85,64.74 174.07,64.74 v2(173.61,65.2)
  BOTTOM w0.305: R119.1 172.76,63.62 172.76,64.43 172.26,64.92 R120.1 173.57,65.15 v2(173.61,65.2)
+VCCPGPPG: length 22.5
  TOP w0.254: v2(194.32,64.89) 194.38,64.97 U1.AD15
  TOP w0.305: v2(176.45,61.69) 175.63,62.51 R121.1 R131.1
  LAY3 w0.254: v2(176.45,61.69) 177.37,62.61 187.43,62.61 189.01,64.19 193.61,64.19 v2(194.32,64.89)
+VCCSA: length 194.3
  TOP w0.127: U1.J27 202.17,72.97 ; U1.J27 202.45,72.69 ; U1.J27 202.73,72.97 ; U1.J27 202.45,73.24 ; U1.K28 202.62,72.5 ; U1.K28 202.9,72.22 ; U1.K28 202.9,72.78 ; 201.99,73.71 U1.G27 ; U1.G27 201.99,73.15 ; U1.G27 202.27,73.43 ; U1.G27 201.71,73.43 ; 200.62,72.69 U1.J23 ; U1.J23 200.62,73.24 ; U1.J23 200.34,72.97 ; U1.J23 200.9,72.97 ; U1.G28 v2(202.45,73.68) ; U1.G28 202.62,73.43 ; U1.G28 202.9,73.15 ; 199.79,73.27 U1.J22 200.05,72.97 ; U1.K27 201.99,72.78 ; U1.K27 202.27,72.5 ; U1.K27 201.99,72.22 ; 200.16,72.22 U1.K23 ; U1.K23 200.16,72.78 ; U1.K23 200.16,72.81 ; U1.K23 v2(200.62,72.27) ; U1.K25 201.08,72.78 ; U1.K25 201.08,72.22 ; U1.K25 200.8,72.5 ; 201.08,73.15 U1.G25 ; U1.G25 200.8,73.43 ; U1.G25 201.08,73.71 ; U1.G25 201.35,73.43 ; 200.44,73.26 U1.G23 ; U1.G23 200.16,73.15 ; U1.G23 v2(200.62,73.68)
  TOP w0.203: 203.82,72.94 U1.K30 203.82,72.14 ; U1.AK25 v2(201.08,63.07) ; U1.AK23 v2(200.16,63.07)
  LAY3 w0.254: v2(245.81,85.94) 245.74,86.01 244.43,86.01 243.77,85.35 239.81,85.35 238.88,86.28 237.84,86.28 235.9,88.23 235.9,88.94 234.11,90.72 232.44,90.72 230.91,92.26 210.69,92.26 210.14,92.8 206.39,92.8 205.92,92.33 204.47,92.33 203.77,93.03 201.61,93.03 200.91,92.33 192.7,92.33 191.57,91.2 169.2,91.2 v2(168.81,90.81)
  LAY3 w0.305: v2(247.76,96.63) 246.89,95.77 246.89,90.67 247.34,90.23 247.95,90.23 248.34,89.84 248.34,86.36 246.89,84.9 239.57,84.9 238.7,85.77 237.78,85.77 235.5,88.04 235.5,88.7 233.94,90.25 232.26,90.25 230.64,91.88 210.41,91.88 209.86,92.42 206.58,92.42 205.99,91.84 204.24,91.84 203.51,92.57 201.87,92.57 201.13,91.84 193.08,91.84 190.77,89.53 190.77,87.29 v2(188.71,85.23)
  BOTTOM w0.203: R223.2 C311.2 C315.2 246.31,85.44 v2(245.81,85.94) 246.3,86.42 247.45,86.42 247.86,86.01 247.86,81.52 246.26,79.92 244.81,79.92 244.53,80.19 R225.1 244.04,80.41 R228.1 243.24,81.2 R237.2
  BOTTOM w0.305: R672.2 247.79,96.66 v2(247.76,96.63) ; 188.71,85 v2(188.71,85.23)
  vias: v1(172.21,90.12) v1(172.98,90.12) v1(173.74,90.12) v1(174.47,90.12) v1(175.24,90.12) v1(176,90.12) v2(200.59,71.6) v2(201.35,71.6) v2(201.39,79.12) v2(201.53,73.68) v2(201.99,71.56) v2(202.45,72.27) v2(202.6,71.56)
+VDDQ_MEM: length 100.6
  TOP w0.152: v2(231.36,20.62) 231.37,20.62 CN1.33 ; U1.BB41 209.31,54.33
  TOP w0.178: U1.BB23 199.34,55.2 199.34,54.06 v2(199.14,53.86) ; v2(212.93,54.21) 212.97,54.28 212.97,54.63 U1.BB47 ; U1.BB32 204.36,55.04 204.35,55.01 v2(204.35,54.26)
  TOP w0.203: C173.2 213.06,53.59 212.93,53.72 v2(212.93,54.21) ; U1.BB51 v2(215.43,54.28)
  TOP w0.254: CN1.123 v2(208.86,20.62) ; CN1.178 193.11,15.44 192.8,15.75 v2(192.62,15.75) ; CN1.54 v2(226.11,15.16) ; CN1.241 177.36,20.26 177.14,20.03 v2(176.87,20.03) ; v2(201.08,15.72) 200.84,15.72 200.62,15.49 CN1.148 ; CN1.112 211.62,15.2 v2(211.61,15.2) ; CN1.163 196.86,20.81 196.67,20.62 v2(196.36,20.62) ; v2(199.65,15.73) 199.36,15.73 199.11,15.49 CN1.154 ; CN1.118 210.11,15.38 v2(210.15,15.41) ; CN1.75 220.86,19.57 220.16,18.86 v2(219.86,18.86) ; CN1.153 199.36,20.62 v2(199.36,20.62) ; C171.2 198.89,53.6 v2(199.14,53.86) ; v2(204.11,15.11) 204.11,15.11 CN1.142 ; v2(208.54,15.13) 208.62,15.06 CN1.124 ; v2(187.86,20.62) 187.87,20.62 CN1.199 ; CN1.159 197.86,20.62 v2(197.86,20.62) ; CN1.135 v2(205.86,20.62) ; C175.2 209.33,52.77 v2(209.33,53.37) 209.33,54.31 209.31,54.33 ; v2(200.86,20.62) 200.86,20.62 CN1.147 ; C174.2 204.11,53.18 204.31,53.39 204.31,54.22 v2(204.35,54.26) ; CN1.130 207.11,15.17 v2(207.12,15.17) ; v2(214.62,16.33) 214.94,16.33 215.62,15.65 CN1.96 ; CN1.160 197.62,15.06 v2(197.62,15.06) ; U1.AU35 v2(207.02,58.24) ; U1.AU28 v2(203.36,58.24) ; CN1.129 v2(207.36,20.62) ; v2(210.52,20.58) 210.36,20.74 CN1.117 ; U1.AU42 v2(210.68,58.24) ; U1.AU23 v2(200.62,58.24) ; CN1.111 v2(211.86,20.62) ; U1.AM40 209.28,61.19 v2(208.85,60.8) ; CN1.12 236.61,15.16 v2(236.61,15.16) ; CN1.141 v2(204.36,20.62) ; CN1.220 v2(182.61,15.17) ; CN1.136 v2(205.62,15.16)
  TOP w0.305: U1.AL23 v2(199.7,62.39)
  LAY3 w0.254: v2(199.7,62.39) 199.7,61.75 200.16,61.3 200.16,58.7 v2(200.62,58.24)
  LAY6 w0.305: v2(236.06,39.78) 239.58,43.31 v2(239.58,45.89)
  BOTTOM w0.203: 234.26,36.57 U29.28 ; U29.2 236.95,39.2 236.62,39.53 236.31,39.53 v2(236.06,39.78)
  BOTTOM w0.305: v2(234.99,44.68) R546.2 ; v2(239.58,45.89) U4.5 238.66,45.35 236.46,47.55 236.46,49.08 R811.2 v2(235.9,49.12) ; v2(212.93,54.21) 215.35,54.21 v2(215.43,54.28) ; v2(228.06,36.69) C698.2 231.86,36.57 234.26,36.57 ; 182.91,17.82 178.41,17.82 177.69,18.54 177.69,19.68 177.35,20.03 v2(176.87,20.03)
  vias: v1(203.59,24.52) v1(203.59,23.76) v1(204.35,24.52) v1(204.35,23.76) v1(218.45,39.14) v1(218.45,38.38) v1(218.45,37.61)
+VDDQ_VTT: length 110.6
  TOP w0.305: CN1.258 173.11,11.94
  LAY3 w0.305: v1(232.97,41) 232.99,40.99 v1(232.99,40.23)
  LAY3 w0.762: v1(232.99,40.23) 232.99,36.37 246.5,22.86 246.5,20.67 247.43,19.74 247.43,17.04 240.26,9.88 180.84,9.88 179.4,11.32 v1(177.87,11.32)
  BOTTOM w0.203: U29.31 235.52,37.77 235.16,38.13 ; U29.29 234.88,36.97
  BOTTOM w0.305: 234.88,36.97 234.78,36.97 233.83,37.93 ; 235.16,38.13 235.14,38.13 ; 235.14,38.13 234.66,38.6 ; 235.14,38.13 235.05,38.13 ; 234.71,37.79 235.05,38.13 ; 235.05,38.13 234.69,38.13
  BOTTOM w0.406: R820.2 232.61,42.07
AGND: length 187.3
  TOP w0.203: 33.95,29.72 37.1,29.72 37.63,29.2 37.63,27.53 36.8,26.7 35.87,26.7 35.39,27.17 30.97,27.17 30.04,26.24 J3.5 ; C421.2 22.62,26.44 12.57,26.44 v2(11.86,25.72) 9.73,23.6 9.73,19.86 7.98,18.11 v2(7.68,18.11) 7.26,18.52 7.26,19.78 8.49,21.01 8.49,24.27 12.01,27.78 24.29,27.78 C422.2
  TOP w0.305: R364.2 25.22,27.65 C422.2 v2(24.43,28.33) 24.43,28.93 27.25,31.75 31.92,31.75 33.95,29.72 ; C418.2 32.26,29.25 J3.2 ; B1.2 57.04,8.69 57.04,9.32 56.56,9.8 54.56,9.8 52.5,7.74 17.28,7.74 14.97,10.05 14.97,11.4 15.31,11.74 15.83,11.74 16.1,11.48 16.1,10.16 17.64,8.61 52.08,8.61 54.87,11.4 58.08,11.4 58.49,10.99 CN42.1 58.49,9.28 59.79,7.98 CN42.E2 ; v2(23.2,24.48) R363.2 C421.2 ; C419.2 v2(27.46,24.85)
  BOTTOM w0.203: U16.25 v2(11.63,16.21) 11.63,15.55 v2(11.65,15.54) ; v2(16.53,12.84) 16.71,13.02 R357.2 ; C428.2 7.87,16.84 v2(7.36,16.33) ; v2(7.68,18.11) 7.92,17.86 C432.1 ; v2(11.85,22.5) 12.4,22.5 12.73,22.17 U16.38
  BOTTOM w0.305: C414.2 v2(37.78,20.67) ; Q36.2 19.26,10.47 v2(19.26,10.75) ; C413.2 31.09,20.76 v2(31.07,20.78) ; C444.1 v2(7.06,24.69)
  BOTTOM w0.406: C441.1 12.15,25.43 v2(11.86,25.72) C442.2
  vias: v2(6.62,19.5) v2(6.63,18.91) v2(10.03,14.07)
AVDD2_AUDIO: length 44.8
  LAY3 w0.406: v2(7.57,25.94) 7.66,25.84 7.66,23 5.56,20.89 5.56,16.07 9.1,12.53 14.01,12.53 14.8,11.74 14.8,10.74 15.82,9.72 20.35,9.72 23.76,13.13 v2(23.76,14.77)
  BOTTOM w0.203: C441.2 12.15,23.77 13.53,22.39 U16.40
  BOTTOM w0.406: C441.2 11.24,24.1 C442.1 10.57,24.22 10.2,24.59 10.2,25.59 FB12.1 8.62,25.93 FB11.1 v2(7.57,25.94) ; FB10.1 v2(23.76,14.77)
AVDD33: length 6.7
  BOTTOM w0.203: U95.4 76.81,96.91 C2788.2
  BOTTOM w0.305: FB20.1 80.12,94.88 79.65,94.41 77.81,94.41 77.36,94.87 C2789.1 77.36,95.36 C2788.2
GND: length 1730.6
  TOP w0.102: v2(206.72,75.97) 207.12,76.37 207.12,78.28 v2(206.72,78.67)
  TOP w0.152: U1.BB60 220.4,55.13 220.4,54.26 v2(220.42,54.23) ; R729.1 231.85,77.01 R726.1
  TOP w0.178: v2(227.93,63.86) 227.91,63.8 227.75,63.64 U1.AG71 ; v2(210.64,54.2) 210.61,54.22 U1.BB43 ; U1.H71 227.75,73.24 v2(227.84,73.32) ; v2(200.63,54.19) 200.68,54.24 200.68,54.75 U1.BB26 ; v2(227.93,58.63) 227.75,58.63 U1.AT71 ; U1.BB30 203.03,54.5 203.03,54.11 v2(202.9,53.98) ; v2(217.74,54.23) 217.78,54.27 217.78,54.76 U1.BB55 ; U1.BB18 196.93,54.26 v2(196.9,54.23) ; v2(227.93,60.9) 227.85,60.98 227.12,60.98 U1.AM71 ; U1.BB38 208,55.14 208,54.19 v2(207.97,54.16) ; v2(205.7,53.55) 205.66,53.59 205.66,54.88 U1.BB34 ; v2(222.73,54.23) 222.74,54.24 222.74,54.62 U1.BB64
  TOP w0.203: CN1.89 v2(217.36,20.62) ; CN1.107 212.86,20.49 213.34,20.01 v2(213.39,20.01) 213.49,20.01 213.86,20.38 CN1.103 ; D20.P v2(64.51,22.5) ; CN1.35 230.86,20.37 231.21,20.03 v2(231.36,20.03) ; v2(227.84,71.87) 227.73,71.88 U1.K71 ; v2(216.11,16.33) 216.29,16.33 217.11,15.51 CN1.90 ; D7.P 10.81,91.52 v2(10.83,91.5) ; v2(221.62,16.92) 221.13,16.92 220.11,15.9 CN1.78 ; v2(235.11,15.16) 235.11,15.16 CN1.18 ; U1.AW53 217.04,57.1 217.07,57.13 217.36,57.13 217.4,57.1 U1.AW55 218.27,57.1 218.3,57.13 218.59,57.13 218.62,57.1 U1.AW57 219.54,57.1 219.57,57.13 219.87,57.13 219.9,57.1 U1.AW60 220.77,57.1 220.8,57.13 221.09,57.13 221.12,57.1 U1.AW62 221.99,57.1 222.03,57.13 222.32,57.13 222.35,57.1 U1.AW64 222.89,57.15 223.85,57.15 U1.AW66 224.12,57.24 224.2,57.15 224.21,57.15 v2(224.39,56.97) U1.AY66 U1.BA66 ; U1.BA2 U1.BA1 186.16,54.92 v2(186.16,54.65) ; U1.J42 v2(210.68,72.27) ; v2(37.28,92.78) 37.26,92.76 D2513.P ; CN1.43 228.86,20.29 229.12,20.03 v2(229.36,20.03) 229.63,20.03 229.86,20.27 CN1.39 ; U13.3 v2(5.9,92.01) ; C324.1 236.3,82.46 v2(236.49,82.65) ; v2(176.43,82.29) 176.23,82.29 C808.1 ; v2(227.37,20.03) 227.56,20.03 227.86,20.34 CN1.47 ; CN1.23 233.86,20.23 234.06,20.03 v2(234.36,20.03) 234.57,20.03 234.86,20.33 CN1.19 ; v2(239.71,20.74) 239.37,21.08 CN1.1 ; v2(210.42,49.5) 210.18,49.5 209.46,50.22 C175.1 ; U1.AF63 221.85,63.88 221.85,63.18 U1.AH63 ; v2(231.08,75.17) 230.99,75.08 R725.1 ; U1.F40 v2(208.85,73.68) U1.F38 ; R722.1 230.46,78.29 v2(230.81,77.93) 231.01,77.73 R727.1 231.29,77.73 R724.1 ; U1.F35 v2(207.02,73.68) U1.F37 ; CN1.86 v2(218.11,15.18) ; R91.1 182.85,73.45 v2(183.01,73.61) ; v2(225.5,54.14) 225.43,54.14 U1.BB67 ; v2(232.86,19.45) 232.68,19.45 231.86,20.26 CN1.31 ; CN1.9 v2(237.37,20.62) ; CN1.72 v2(221.62,15.16) ; CN1.6 238.11,15.16 v2(238.11,15.16) ; 197.39,57.13 197.36,57.1 U1.AW18 196.45,57.1 196.41,57.13 196.12,57.13 196.09,57.1 U1.AW16 195.64,57.1 v2(195.13,57.61) 194.62,57.1 U1.AW14 194.02,57.1 193.99,57.13 193.7,57.13 193.67,57.1 U1.AW12 192.9,57.1 v2(192.39,57.61) 192.09,57.31 U1.AW10 191.6,57.1 191.57,57.13 191.28,57.13 191.25,57.1 U1.AW8 190.46,57.1 190.43,57.13 190.13,57.13 190.1,57.1 U1.AW6 ; 197.39,57.13 197.42,57.16 U1.AU20 ; 197.39,57.13 197.69,57.13 197.72,57.1 U1.AW21 ; v2(232.11,15.16) 232.11,15.16 CN1.30 ; U1.AV68 224.88,57.44 224.88,57.81 224.83,57.85 224.83,58.04 224.88,58.21 U1.AT68 224.88,59.02 224.85,59.05 224.85,59.34 224.88,59.37 U1.AP68 224.88,60.24 224.85,60.27 224.85,60.57 224.88,60.6 U1.AM68 ; CN1.10 237.11,15.58 237.87,16.33 v2(238.11,16.33) ; v2(210.68,73.68) U1.F42 ; v2(225.37,18.86) 226.17,18.86 226.86,19.55 CN1.51 ; U1.F32 v2(205.19,73.68) U1.F33 ; CN1.65 223.37,20.32 223.65,20.03 v2(223.86,20.03) 224.03,20.03 224.37,20.37 CN1.61 ; CN1.85 v2(218.36,20.62) ; CN1.22 234.11,15.8 234.64,16.33 v2(235.11,16.33) ; CN1.27 232.86,20.62 v2(232.86,20.62) ; U1.AK22 198.73,62.13 U1.AK21 198.23,62.28 v2(198.23,62.38) ; v2(227.61,15.16) 227.61,15.16 CN1.48 ; CN1.69 v2(222.37,20.62) ; v2(37.82,89.83) 37.92,89.73 38.18,89.73 U2524.3 ; U1.AW51 215,57.1 214.97,57.13 214.68,57.13 214.65,57.1 U1.AW49 213.75,57.1 213.72,57.13 213.42,57.13 213.39,57.1 U1.AW47 212.58,57.1 212.55,57.13 212.26,57.13 212.23,57.1 U1.AW45 211.35,57.1 211.32,57.13 211.03,57.13 211,57.1 U1.AW43 210.13,57.1 210.1,57.13 209.8,57.13 209.77,57.1 U1.AW41 209.31,57.14 v2(208.85,57.61) 208.34,57.1 U1.AW38 207.63,57.1 207.6,57.13 207.3,57.13 207.27,57.1 U1.AW36 206.4,57.1 206.37,57.13 206.07,57.13 206.04,57.1 U1.AW34 205.56,57.22 205.19,57.59 204.7,57.1 U1.AW32 203.87,57.1 203.84,57.13 203.55,57.13 203.52,57.1 U1.AW30 202.65,57.1 202.61,57.13 202.32,57.13 202.29,57.1 U1.AW28 201.42,57.1 201.39,57.13 201.09,57.13 201.06,57.1 U1.AW26 200.19,57.1 200.16,57.13 199.87,57.13 199.84,57.1 U1.AW23 ; U1.AL64 222.7,61.29 222.75,61.25 223.13,61.25 223.18,61.29 U1.AL65 223.34,61.29 223.39,61.25 223.76,61.25 223.81,61.29 U1.AL66 ; 169.07,60.6 U67.E1 169.57,60.6 ; v2(236.61,15.75) 236.41,15.75 236.11,15.46 CN1.14 ; U1.AL52 v2(215.25,62.36) ; U1.AD20 198.01,65.42 198.45,65.42 U1.AD21 ; U1.J38 v2(208.85,72.27) ; U1.K63 221.67,72.5 U1.K61 ; v2(189.11,62.61) 189.26,62.76 U1.AH6 ; U1.AL55 v2(217.08,62.36) ; D22.P v2(48.92,22.51) ; CN1.64 223.61,16.68 223.38,16.92 v2(223.11,16.92) ; D21.P v2(48.92,18.54) ; CN1.40 229.61,15.36 229.22,15.75 v2(229.11,15.75) 228.94,15.75 228.61,15.42 CN1.44 ; CN1.15 v2(235.86,20.62) ; U1.J28 v2(203.36,72.27) ; CN1.60 v2(224.61,15.16) ; v2(230.61,16.92) 231.2,16.92 231.79,16.33 v2(232.11,16.33) 232.3,16.33 233.11,15.51 CN1.26 ; U1.AA68 225.21,66.6 v2(224.88,66.28) ; CN1.36 230.61,15.16 v2(230.61,15.16) ; v2(32.85,92.71) 32.81,92.67 U2523.3 ; CN1.77 220.36,20.28 220.12,20.03 v2(219.86,20.03) 219.6,20.03 219.36,20.27 CN1.81 ; v2(135.07,84.62) 135.52,84.17 R455.2 135.22,83.45 U27.3 ; v2(182.97,70.36) R117.2 183.56,70.37 R116.2 ; CN1.68 222.61,15.48 222.88,15.75 v2(223.11,15.75) ; U1.D48 U1.D47 213.47,75.49 213.09,75.49 213.06,75.47 212.77,75.47 212.75,75.49 212.36,75.49 U1.D45 U1.D44 ; U1.AF4 v2(187.99,64) U1.AF2 U1.AF1 185.94,64 v2(185.93,63.99) ; Q49.2 v2(100.61,15.33) ; U1.AL48 v2(213.42,62.36) ; v2(62.79,63.05) 62.66,63.05 C481.1 ; D8.P v2(7.63,91.98) ; CN1.57 v2(225.37,20.62) ; U1.AV1 186.01,57.31 v2(185.87,57.18) ; v2(140.56,90.65) 140.2,90.29 C2764.1 ; U1.AL45 v2(211.59,62.36) ; C173.1 213.06,51.91 v2(213.64,51.33) ; CN1.93 v2(216.36,20.62) ; U1.J25 v2(201.53,72.27) ; v2(222.37,19.45) 222.33,19.48 221.91,19.48 221.36,20.03 CN1.73 ; U1.J35 v2(207.02,72.27) ; R3106.2 v2(124.59,89.79) ; U1.AM68 224.69,61.08 v2(224.39,60.78) ; U1.AM68 224.88,61.47 224.8,61.56 224.8,61.83 225.21,62.24 U1.AK68 225.21,62.43 U1.AH67 ; U1.AL58 v2(218.91,62.36) ; v2(133.94,81.19) 133.83,81.08 C510.1 ; R130.2 225.38,84.94 v2(225.11,84.67) ; v2(201.53,62.36) 201.76,62.13 U1.AK27 v2(201.99,63.07) ; CN1.99 v2(214.86,20.62) ; U6.3 v2(170.24,55.6) ; D2512.P 34.45,92.28 v2(34.4,92.34) ; v2(189.67,56.59) U1.BA6 U1.BB6 ; CN1.102 214.11,15.36 214.5,15.75 v2(214.62,15.75) 214.82,15.75 215.11,15.45 CN1.98 ; D19.P v2(64.51,18.66) ; CN1.5 238.37,20.27 237.54,19.45 v2(237.37,19.45) ; CN1.56 225.61,15.56 225.8,15.75 v2(226.11,15.75) 226.29,15.75 226.61,15.42 CN1.52 ; CN1.82 v2(219.11,15.16) ; U1.K70 225.85,71.88 v2(225.69,72.09) ; CN1.2 v2(239.11,15.18) ; U1.J32 v2(205.19,72.27) ; v2(196.93,67.4) U1.Y19 196.86,67.49 U1.V18 v2(196.93,67.4)
  TOP w0.254: v2(194.62,16.34) 194.3,16.34 193.62,15.65 CN1.176 ; U1.F13 v2(194.22,74.32) 194.25,74.32 194.67,74.7 U1.E15 ; 195.55,69.07 U1.T17 196.1,68.51 196.46,68.51 U1.T18 196.6,68.67 v2(196.91,69.09) 197.25,69.5 U1.P19 197.58,69.83 v2(197.58,69.93) ; 195.55,69.07 195.95,69.47 U1.P17 ; 195.55,69.07 194.89,69.07 194.65,68.82 U1.T15 ; U1.V18 196.39,68.04 196.17,68.04 U1.V17 ; v2(179.11,16.34) 178.91,16.34 178.57,16 178.57,15.68 178.12,15.23 v2(178.12,15.17) 178.11,15.17 CN1.238 ; v2(221.14,65.72) 221.49,65.38 U1.AD62 ; U1.AN32 v2(205.19,60.15) ; CN1.239 177.87,20.01 177.3,19.45 v2(176.87,19.45) ; U1.AJ15 194.08,62.79 U1.AH13 ; v2(213.42,74.3) 213.39,74.3 U1.E46 v2(213.42,74.95) 213.48,75.01 U1.D47 ; v2(198.93,70.71) 198.93,70.61 198.66,70.34 U1.N21 198.35,70.54 198.35,70.68 197.9,71.12 U1.L20 ; 225.54,65.24 v2(225.54,65.35) ; 225.54,65.24 225.54,65.22 U1.AE69 ; 225.54,65.24 U1.AE68 ; v2(224.39,56.97) 224.43,56.97 224.87,57.39 U1.AV68 v2(225.35,57.24) U1.AV69 U1.AV70 U1.AV71 227.8,57.24 v2(227.93,57.11) ; CN1.218 183.11,15.62 183.84,16.34 v2(184.11,16.34) ; v2(208.87,75.04) 209.2,75.37 U1.D39 v2(209.2,75.97) U1.B39 ; v2(198.23,63.21) 198.23,63.31 U1.AG21 ; v2(198.23,63.21) 197.9,62.89 U1.AJ20 198.23,62.47 v2(198.23,62.38) ; v2(198.23,63.21) 197.9,63.54 U1.AG20 197.77,63.49 197.39,63.49 U1.AG19 197.25,63.52 197.06,63.32 v2(196.92,63.32) ; U1.AE66 U1.AE67 ; U1.AE66 U1.AE65 ; U1.AE66 223.58,65.23 ; U1.AE67 U1.AE68 ; U1.AE67 224.89,65.24 ; v2(221.65,60.8) U1.AM61 U1.AK63 v2(222.3,62.62) ; U1.D14 v2(194.33,75.97) U1.B14 ; U1.AM13 193.25,61.7 192.38,61.7 v2(192.27,61.82) U1.AK11 192.99,62.61 v2(193.44,62.61) 193.72,62.96 U1.AH13 ; v2(195.13,58.88) U1.AR15 ; 195.72,65.72 195.72,65.73 U1.AB16 v2(194.97,66.57) U1.AB15 193.81,65.3 U1.AD13 ; 195.72,65.72 U1.AD16 v2(195.62,64.89) U1.AF17 v2(196.28,64.05) ; 195.72,65.72 196.27,65.72 U1.AB18 ; v2(74.41,64.5) 74.38,64.54 CN16.16 ; U1.AU38 v2(208.85,57.61) ; U1.D48 v2(214.16,75.97) U1.B48 ; U1.BB70 227.74,54.82 v2(227.93,55.02) 227.66,55.29 U1.BA71 ; U1.F28 v2(202.45,74.32) U1.F27 ; R728.1 231.29,74.25 R730.1 231.29,74.46 232,75.17 v2(232.39,75.17) ; U1.L17 195.91,71.17 v2(195.63,70.81) 195.35,71.17 U1.L16 U1.K16 ; v2(198.23,68.22) 198.23,68.31 198.56,68.64 U1.T21 U1.P21 199.15,69.5 v2(199.18,69.53) ; U1.E18 v2(196.96,74.95) 196.81,75.1 U1.D18 v2(196.81,75.97) U1.B18 ; CN16.19 75.88,66.49 v2(76.01,66.62) ; v2(224.7,73.68) U1.G66 224.03,73.65 v2(223.68,73.65) ; v2(176.62,15.17) 176.61,15.17 CN1.244 ; U1.AL4 v2(188,61.35) U1.AL2 ; U1.BA10 U1.AW10 ; U1.AF10 192.17,63.82 v2(192.17,63.68) ; U1.G48 v2(214.33,73.68) ; CN1.252 174.61,15.46 174.91,15.75 v2(175.11,15.75) 175.34,15.75 175.61,15.48 CN1.248 ; U1.W13 v2(193.44,66.88) ; U1.B62 v2(221.59,75.97) U1.D62 221.59,75.01 v2(221.65,74.95) v2(221.65,74.3) v2(221.65,73.65) ; v2(222.56,60.78) 222.35,60.78 U1.AN63 222.22,60.44 222.36,60.3 222.39,60.3 v2(222.56,60.15) ; U1.AB8 v2(190.27,65.81) ; 199.72,73.74 199.26,73.49 U1.G22 199.31,73.37 199.31,72.56 U1.K22 ; 199.72,73.74 199.69,73.74 199.3,74.08 U1.F22 ; 199.72,73.74 v2(199.77,73.74) U1.F23 ; U1.J8 v2(191.47,72.41) ; U1.AF63 U1.AE64 ; U1.AE64 U1.AE65 ; U1.AE64 222.6,64.97 v2(222.93,65.3) 222.93,65.23 U1.AE65 ; U41.7 164.03,47.43 164.04,47.43 v2(164.58,47.43) ; U1.BA57 v2(219.08,56.59) U1.AW57 ; U1.T4 188.41,69.3 v2(188.13,69.02) 187.85,69.3 U1.T2 ; U1.D58 v2(219.11,75.97) U1.B58 ; U1.AP20 v2(197.87,59.51) 197.87,60.11 197.42,60.51 U1.AN20 ; CN1.230 180.11,15.41 180.46,15.75 v2(180.61,15.75) 180.82,15.75 181.11,15.46 CN1.226 ; v2(196.92,63.32) U1.AG18 v2(196.28,64.05) ; v2(196.92,63.32) 196.6,63 U1.AJ18 196.61,62.79 196.79,62.61 196.79,62.15 U1.AK18 196.92,61.48 v2(196.96,61.42) ; U1.AU20 v2(197.87,58.24) U1.AT20 ; CN1.192 v2(189.61,15.17) ; CN1.201 187.36,20.35 187.68,20.03 v2(187.86,20.03) ; CN1.175 193.86,20.62 v2(193.86,20.62) ; U1.AK8 190.77,61.92 v2(190.77,61.65) 190.77,61.44 U1.AM8 ; v2(224.25,71.79) U1.K67 U1.K68 v2(225.69,72.09) ; v2(189.65,58.88) U1.AR5 ; U1.AR11 192.48,58.88 v2(192.39,58.88) 192.39,59.51 U1.AP10 ; U1.AR50 v2(215.25,58.88) U1.AR52 v2(216.16,58.88) ; R718.1 182.13,50.21 v2(182.26,50.07) ; U1.AW18 v2(196.93,56.41) U1.BA18 ; U1.B44 v2(211.68,75.97) U1.D44 ; CN1.223 v2(181.87,20.62) ; U1.K66 v2(223.6,71.79) U1.K65 U1.K64 ; v2(222.3,62.62) U1.AH63 ; v2(222.3,62.62) U1.AH64 ; U1.F33 205.98,74.41 v2(206.09,74.41) 206.23,74.41 U1.F35 206.87,74.39 v2(207.03,74.39) 207.17,74.39 U1.F37 207.76,74.37 v2(207.95,74.37) 208.1,74.37 U1.F38 208.7,74.39 v2(208.87,74.39) 208.99,74.39 U1.F40 209.56,74.33 v2(209.77,74.33) 209.93,74.33 210.18,74.08 U1.F42 ; v2(188.98,70.08) U1.N6 ; U1.D25 201.72,75.5 U1.D26 v2(201.77,75.97) 201.58,76.15 U1.C25 ; U1.BA62 v2(221.56,56.59) U1.AW62 ; U1.AW14 v2(194.51,56.44) U1.BA14 ; v2(190.56,73.68) 190.36,73.68 U1.G6 ; v2(191.54,70.08) 191.54,70.09 U1.N10 192.17,70.22 v2(192.17,70.08) ; CN1.94 v2(216.11,15.16) ; CN1.234 v2(179.11,15.17) ; U1.AP58 v2(219.82,59.51) ; U1.AM55 v2(217.99,60.8) ; R731.1 231.3,75.39 v2(231.08,75.17) ; U1.U69 v2(226.18,68.11) U1.U70 ; U1.B30 v2(204.24,75.97) U1.D30 204.24,74.39 v2(204.28,74.36) 204.46,74.36 U1.F32 ; U1.B34 v2(206.72,75.97) U1.D34 ; U1.P20 197.59,69.93 v2(197.58,69.93) ; U1.AE65 223.58,65.23 ; U1.AR48 v2(214.33,58.88) ; U1.B66 v2(224.07,75.97) U1.D66 ; v2(162.29,47.77) 162.53,47.52 U41.8 ; v2(191.54,67.95) U1.U10 191.86,68.28 v2(192.19,67.95) ; U1.AE69 226.18,65.23 v2(226.18,65.4) ; U1.AE69 U1.AE68 ; v2(197.58,69.93) 197.58,69.94 U1.N19 197.26,70.38 v2(196.92,70.81) 196.65,71.17 U1.L18 ; U1.D6 189.4,75.94 v2(189.38,75.97) 189.25,76.1 189.22,76.1 189.16,76.15 U1.C5 ; U2.3 v2(166.9,51.89) ; U1.AP63 v2(222.56,59.51) ; U1.L11 v2(192.17,71.02) ; U1.T15 U1.R13 ; U1.T15 194.97,68.35 v2(194.97,68.24) U1.V16 U1.Y17 ; U1.AN28 v2(203.36,60.15) ; U1.AL32 v2(204.28,62.36) ; v2(221.65,73.65) 221.81,73.49 U1.G63 222.21,73.49 v2(222.67,73.03) 222.67,72.23 U1.K64 ; v2(221.65,73.65) 221.65,72.96 U1.K61 ; U1.AE68 224.89,65.22 224.89,65.24 ; CN1.209 185.36,20.05 185.97,19.45 v2(186.36,19.45) ; U1.A67 224.74,77.64 225.07,77.97 v2(225.07,78.11) ; U1.F68 U1.D69 ; U1.D69 v2(225.93,75.11) 225.93,75.11 U1.D69 ; U1.L4 188.17,71.95 v2(187.99,71.77) 187.81,71.95 U1.L2 ; v2(217.78,49.22) 217.78,49.23 R3125.2 R3124.2 ; CN1.193 189.36,20.62 v2(189.36,20.62) ; U1.AT2 187.81,58.69 187.82,58.69 v2(187.99,58.69) 188.16,58.69 188.17,58.69 U1.AT4 ; U1.AN37 v2(207.93,60.15) U1.AN38 ; v2(220.73,74.33) v2(220.73,73.68) U1.G60 ; U1.BA36 v2(206.83,56.59) U1.AW36 ; CN1.185 191.36,20.25 191.15,20.03 v2(190.86,20.03) 190.67,20.03 190.36,20.33 CN1.189 ; v2(185.8,76.69) 186.01,76.49 U1.C1 ; v2(191.47,58.88) U1.AR8 ; v2(182.95,66.63) 183.13,66.81 C231.1 ; CN1.171 194.86,20.62 v2(194.86,20.62) ; U1.AR42 v2(210.68,58.88) U1.AT42 ; v2(227.94,76.99) U1.B71 U1.A70 ; U1.AU32 205.19,57.59 ; U1.AW6 189.67,57.06 v2(189.67,56.59) ; CN1.180 v2(192.62,15.17) ; U1.AN23 v2(200.62,60.15) ; 224.89,65.24 v2(224.89,65.35) ; U1.F8 191.24,74.08 v2(191.47,74.32) ; U1.AN30 v2(204.28,60.15) ; v2(211.79,56.59) U1.BA45 ; R729.1 230.98,76.46 v2(230.89,76.56) 230.46,76.13 R721.2 ; CN1.222 182.11,15.46 182.41,15.75 v2(182.61,15.75) ; U1.AR43 v2(211.59,58.88) ; v2(196.12,15.75) 195.95,15.75 195.62,15.42 CN1.168 ; v2(198.88,64.89) 198.88,64.98 U1.AD21 U1.AB21 198.56,66.24 v2(198.88,66.57) 198.88,66.66 U1.Y21 U1.Y20 ; U1.G58 v2(219.82,73.68) ; U1.AP35 v2(207.02,59.51) ; U1.E6 v2(190.56,74.95) ; CN1.184 191.62,15.34 191.2,15.75 v2(191.11,15.75) 190.83,15.75 190.62,15.54 CN1.188 ; U1.AR23 v2(200.62,58.88) U1.AT23 ; U1.AW49 v2(214.2,56.59) U1.BA49 ; U1.K16 195.71,72.42 196.14,72.42 U1.H18 U1.K18 ; U1.K16 195.13,72.19 v2(195.13,73.05) U1.H15 ; U1.J11 v2(193.3,72.41) U1.J13 ; U1.AR55 v2(217.99,58.88) ; U1.BA53 v2(216.6,56.59) U1.AW53 ; v2(224.39,60.78) 223.91,61.27 U1.AL66 ; U1.AW8 190.86,57.34 191.06,57.55 191.42,57.55 v2(191.47,57.61) ; C804.2 v2(164.75,40.98) ; U1.BA32 v2(204.36,56.59) U1.AW32 ; U1.K64 U1.K63 ; U1.AR35 v2(207.02,58.88) U1.AT35 ; U1.G55 v2(217.99,73.68) ; CN1.167 195.86,20.4 196.23,20.03 v2(196.36,20.03) ; CN1.243 v2(176.87,20.62) ; U1.E56 v2(218.91,74.95) ; CN1.181 192.36,20.62 v2(192.36,20.62) ; U1.AW28 v2(201.85,56.59) U1.BA28 ; U1.AA2 187.84,66.65 v2(188.04,66.85) 188.24,66.65 U1.AA4 ; U1.AM60 v2(220.73,60.8) ; CN16.3 67.88,66.27 v2(68.13,66.52) ; U1.R13 v2(193.44,70.08) U1.N13 193.81,70.66 v2(193.44,71.02) ; U1.R13 v2(193.44,69.01) ; v2(227.84,75.17) 227.71,75.04 U1.E71 ; v2(188.79,77.97) U1.A5 ; U1.U66 v2(224.23,68.11) U1.U67 ; CN1.196 188.61,15.17 188.62,15.17 188.62,15.49 189.46,16.34 v2(189.61,16.34) ; U1.D53 v2(216.63,75.97) U1.B53 ; U1.E50 v2(215.25,74.95) ; 223.58,65.23 v2(223.58,65.3) ; CN1.227 180.87,20.35 180.54,20.03 v2(180.36,20.03) 180.23,20.03 179.87,20.39 CN1.231 ; U1.AT28 v2(203.36,58.88) U1.AR28 ; v2(210.68,73.68) 210.88,73.68 U1.G43 v2(211.59,73.68) ; v2(192.39,57.61) U1.AU10 ; U1.E11 v2(193.3,74.95) U1.D11 U1.D10 v2(191.85,75.97) U1.B10 ; CN1.247 175.87,20.38 175.51,20.03 v2(175.36,20.03) 175.12,20.03 174.87,20.29 CN1.251 ; CN1.206 186.11,15.45 185.81,15.75 v2(185.61,15.75) 185.31,15.75 185.11,15.56 CN1.210 ; U56.5 v2(173.95,80.31) ; U1.G5 v2(189.65,73.68) ; U1.AD19 197.46,65.1 197.7,65.1 U1.AD20 ; U1.AN33 v2(206.1,60.15) ; U1.AH13 194.19,63.45 194.19,64 U1.AF15 U1.AG16 v2(195.62,63.21) 195.95,63.55 U1.AG17 195.95,63.73 v2(196.28,64.05) ; U1.E53 v2(217.08,74.95) ; U1.AD8 v2(190.27,64.75) ; v2(178.36,20.03) 178.66,20.03 178.87,20.23 CN1.235 ; v2(202.45,62.36) U1.AL28 ; U1.AP68 v2(225.49,59.81) U1.AP70 ; v2(222.93,66.28) U1.AA65 ; U1.F1 v2(186.09,74.6) ; v2(195.42,81.35) 195.53,81.35 C208.1 ; v2(223.48,60.78) 223.25,61.01 U1.AL65 ; v2(198.79,60.78) 198.72,60.78 198.33,61.13 U1.AM21 ; U1.AM25 v2(201.53,60.8) ; U1.B22 v2(199.29,75.97) U1.D22 199.29,75.45 v2(198.79,74.95) U1.E21 ; U1.AN35 v2(207.02,60.15) ; U1.W9 v2(190.9,66.88) ; U1.AN40 v2(209.76,60.15) ; U1.AM43 211.43,60.9 211.75,60.9 U1.AM45 212.51,60.8 212.57,60.8 U1.AM46 v2(213.42,60.8) ; U1.G45 v2(212.51,73.68) ; U1.AT63 v2(222.56,58.88) U1.AR63 ; U1.AP18 v2(196.96,59.51) ; U1.AR16 v2(196.05,58.88) ; v2(190.27,71.02) U1.L8 ; U1.AK68 225.38,62.49 v2(225.69,62.49) 225.87,62.31 U1.AK69 ; U1.G52 v2(216.16,73.68) ; U1.AW41 v2(209.31,56.59) U1.BA41 ; v2(224.21,62.62) U1.AH67 ; U1.AM27 v2(202.45,60.8) ; U1.F2 187.81,74.6 v2(187.99,74.43) 188.17,74.6 U1.F4 ; U1.AL38 v2(207.93,62.36) ; v2(184.11,15.17) 184.11,15.17 CN1.214 ; v2(183.37,20.62) 183.36,20.62 CN1.217 ; v2(189.36,19.45) 189.11,19.45 188.36,20.19 CN1.197 ; U1.AR46 v2(213.42,58.88) ; v2(74.7,66.67) 74.88,66.49 CN16.17 ; U1.AT58 v2(219.82,58.88) U1.AR58 ; CN1.202 v2(187.11,15.17) ; U1.AT56 v2(218.91,58.24) ; U1.AL35 v2(206.1,62.36) ; U1.AN42 v2(210.68,60.15) ; U1.W6 v2(188.98,66.88) ; U1.AP38 v2(208.85,59.51) ; CN1.106 v2(213.11,15.16) ; U1.U63 v2(222.28,68.11) U1.U64 ; v2(223.68,74.95) U1.E65 223.19,74.79 v2(223.68,74.3) ; U1.AP42 v2(210.68,59.51) ; U1.N68 v2(224.88,69.93) ; CN1.172 v2(194.62,15.17) ; U1.N65 v2(222.93,69.93) ; U1.R6 v2(188.98,69.01) ; CN1.213 184.36,20.26 184.6,20.03 v2(184.87,20.03) ; U1.AK16 v2(195.13,61.42) ; U1.AP32 v2(205.19,59.51) ; U1.AP28 v2(203.36,59.51) ; U1.AR45 v2(212.51,58.88) ; U1.AN58 v2(219.82,60.15) ; U1.AR53 v2(217.08,58.88) ; R13.2 v2(169.11,48.75) ; CN1.205 v2(186.36,20.62) ; U1.AP23 v2(200.62,59.51) ; v2(195.13,57.61) U1.AU15 ; U1.AR20 v2(197.87,58.88) ; U1.G10 v2(192.39,73.68) ; 16.3,17.32 16.3,20.62 14.76,22.16 14.76,23.51 v1(15.45,24.2) 15.89,24.2 18.15,21.93 18.15,16.8 12.16,10.8 4.57,10.8 4.2,11.17 4.2,13.28 4.53,13.61 5.12,13.61 5.24,13.5 12.48,13.5 16.3,17.32
  TOP w0.305: CN5.3 v2(85.7,52.67) ; CN26.45 125.27,24.36 v2(125.48,24.57) ; R562.1 v2(40.97,23.47) ; v2(189.7,45.89) 189.32,46.26 R52.1 ; v2(84.36,43.95) 84.36,43.79 84.65,43.49 85.7,43.49 85.88,43.67 CN5.39 ; R717.1 v2(231.41,79) ; C216.1 199.04,81.63 v2(199.2,81.8) ; v2(157.88,45.27) 158.36,45.27 R762.2 ; R436.2 v2(172.6,10.39) ; v2(36.75,65.59) 36.74,65.59 Q64.2 ; C661.2 v2(58.13,14.28) ; R118.2 v2(182.95,68.45) ; C33.1 208.97,80.58 v2(209.21,80.58) ; v2(167.04,60.19) 167.08,60.14 C689.1 ; C174.1 v2(204.11,51.24) ; CN5.45 v2(85.7,42.17) ; R66.1 178.64,65.43 R74.1 ; R636.1 v2(124.44,76.34) ; R723.1 229.86,79.9 v2(229.85,79.9) ; CN5.33 v2(85.7,45.17) ; v2(39.05,70.33) 39.11,70.39 Q63.2 ; R3111.2 138.12,89.07 v2(138.16,89.04) ; R456.2 v2(130.94,83.99) ; v2(125.32,32.06) 125.11,31.86 CN26.75 ; v2(48.44,70.66) 48.26,70.84 Q1.2 ; U5.5 v2(244.46,79.33) ; v2(183.01,72.08) 183.05,72.03 C230.1 ; C610.2 v2(159.55,13.67) ; v2(136.85,88.49) 137.38,87.96 Q76.2 ; CN5.73 v2(87.97,35.17) ; C240.1 v2(191.86,81.31) ; CN5.27 v2(85.61,46.67) ; CN5.51 v2(85.64,40.67) ; CN26.23 v2(122.43,18.86) ; Q74.2 v2(48.26,68.2) ; CN26.63 123.26,28.86 122.98,28.58 v2(122.98,28.32) ; v2(240.63,72.94) 240.65,72.92 C282.2 ; CN5.75 v2(87.97,34.67) ; CN26.18 v2(133.05,17.61) ; R756.1 v2(126.16,76.64) ; CN26.51 v2(125.41,25.86) ; CN5.1 v2(85.69,53.17) ; R3102.1 123.27,78.04 v2(123.27,78.04) ; CN26.57 125.93,27.36 v2(125.98,27.4) ; R755.2 v2(127.48,76.56) ; v2(115.35,85.29) R648.2 R754.2 ; Q47.2 v2(162.59,18.75) ; X1.4 206.69,85.83 v2(206.97,86.11) ; v2(133.06,87.33) 133.07,87.34 Q48.2 ; v2(122.37,20.4) 122.42,20.36 CN26.29 ; R81.1 v2(182.96,57.8) ; v2(122.92,13.88) 122.92,14.45 123.33,14.86 CN26.7 ; R53.1 R51.1 184.27,47.55 v2(184.36,47.47) ; R240.2 v2(90.66,36) ; C228.2 183.53,61.37 R101.2 183.53,60.24 v2(183.29,60) ; U1.AJ4 U1.AL4 ; R557.1 v2(60.6,18.67) ; v2(206.72,78.67) v2(206.72,81.24) 206.47,81.49 206.18,81.49 205.74,81.93 C2.2 205.31,82.8 205,83.1 v2(205,84.91) 205,86.4 205.48,86.88 208.47,86.88 v2(208.48,86.89) 208.75,86.89 209.31,86.33 v2(209.31,84.73) 208.71,84.13 X1.2 208.18,83.1 C1.2 208.47,81.92 207.9,81.34 207.9,78.41 v2(208.27,78.03) ; CN26.1 v2(123.08,13.36) ; CN26.36 v2(132.9,22.11) ; v2(85.65,39.37) 85.85,39.17 CN5.57 ; C608.1 v2(159.36,16.62) ; R830.2 v2(48.16,65.19) ; CN5.71 v2(87.99,35.67) ; U14.3 v2(14.45,91.5) ; R489.2 169.06,10.39 v2(168.84,10.61) ; v1(121.55,87.02) 121.23,87.35 U2529.3 ; C2834.1 129.71,85.16 C992.2 129.52,84.97 v2(128.95,84.97) ; U42.4 179.07,40.22 v2(179.08,40.22) ; R513.1 v2(227.43,50.27) ; CN26.33 123.27,21.36 122.94,21.69 v2(122.94,22.83) 122.97,22.86 CN26.39 125.39,22.86 v2(125.39,22.86) ; CN5.15 v2(85.76,49.67) ; C807.1 169.81,79.82 169.44,80.19 v2(169.44,80.28) ; C32.1 C34.1 204.45,80.97 204.12,80.63 204.12,79.02 v2(204.15,78.99) ; v2(180.82,85.17) 180.81,85.19 180.81,85.69 180.34,86.15 Q66.2 ; CN5.21 v2(85.77,48.17) ; R958.1 v2(121.92,83.06) ; C713.2 v2(41.92,22.47) ; U1.BA23 199.38,56.49 v2(199.41,56.52) ; CN5.9 v2(85.71,51.17) ; v2(121.48,32.98) 121.48,32.19 123.31,30.36 CN26.69 ; v2(179.05,61.72) 179.05,62.01 C225.1 ; R638.1 v2(121.23,79.28) ; R555.2 v2(50.31,57.58) ; CN26.24 v2(133.09,19.11)
  TOP w0.406: R590.1 240.2,82.34 v2(240.2,81.52) ; v2(246.61,19.17) 246.61,18.26 246.14,17.79 244.07,17.79 243.58,18.28 v2(243.58,19.75) 243.58,27.7 244.09,28.2 246.33,28.2 247.52,27.02 CN21.E1 ; v2(235.55,85.83) 235.49,85.9 C302.1 ; C306.1 239.59,83.69 v2(239.91,84.01) ; v2(147.42,84.8) 147.41,84.81 C2773.1 C2772.1 v2(147.5,83.99) ; CN37.6 76.3,86.73 v2(76.36,86.67) ; v2(168.28,45.12) 168.01,45.39 C761.1 ; v2(168.39,45.82) 168.39,45.83 R766.1 ; CN37.3 v2(68.8,89.59) ; Q53.2 156.8,68.77 v2(156.89,68.68) ; C790.1 v2(28.56,62.15) ; R536.1 v2(142.95,49.15) ; v2(116.5,29.49) 116.5,29.49 C398.1 ; C802.1 v2(22.75,62.68) ; C171.1 v2(198.89,51.21) ; U35.1 v2(143.69,49.28) ; C795.1 v2(27.77,79.89)
  TOP w0.508: CN16.E1 65.19,65.53 v2(64.88,65.83) ; R74.1 178.38,65.92 178.51,66.05 v2(178.51,66.25) ; v2(99.69,75) 99.69,75.01 CN3.S4 ; CN14.E2 v2(1.23,8.95) 1.22,8.95 ; CN37.E3 v2(83.42,103.9) ; CN24.4 v2(32.85,92.71) ; v2(1.22,15.31) 1.23,15.3 CN14.E1 ; Q67.2 v2(148.98,43.24) ; v2(246.61,19.17) 247.52,20.08 v2(247.52,21.83) CN21.E1 ; CN37.E4 55.48,103.9 v2(55.21,104.17) ; CN37.E2 v2(58.85,90.93) ; v2(99.48,71.43) 99.72,71.2 CN3.S7 ; CN3.P6 103.16,58.5 104.04,59.38 v2(104.04,59.74) ; CN26.E1 v2(122.88,12.22) ; v2(35.85,92.87) 35.85,92.87 CN24.7 ; CN1.E1 172.19,27.26 v2(172.14,27.21) ; C486.2 45.48,60.83 v2(45.26,60.61) ; U39.2 v2(41.99,20.36) ; CN36.4 v2(5.95,92.95) ; CN36.7 v2(8.95,92.98) ; v2(101.54,79.75) 101.52,79.73 CN3.S1 ; CN1.E2 240.85,28.84 v2(241.98,28.84) ; v2(181.78,46.59) 182.06,46.87 R42.2 R41.2 ; v2(121.48,32.98) 121.5,33 CN26.E2 ; v2(103.22,61.03) 103.21,61.04 CN3.P4 ; U40.2 v2(60.23,14.89) ; v2(249.17,29.7) CN21.E2 ; CN3.P5 v2(103.31,59.77) ; CN25.E1 v2(167.15,14.43) ; CN3.P10 v2(99.72,53.42) ; v2(165.74,14.66) 165.72,14.69 CN25.4 ; CN5.E1 v2(84.39,54.31) ; CN37.E1 v2(84.65,90.87) ; CN5.E2 v2(87.93,33.52) ; v2(99.74,50.87) 99.74,50.88 CN3.P12 ; U24.4 v2(58.29,64.65) ; CN25.E2 v2(167.15,17.85) ; CN16.E2 v2(79.44,63.56) ; C609.1 v2(162.49,20.79)
  TOP w1.524: CN24.E2 27.95,99.08 CN24.E4 ; CN24.E1 43.75,99.08 CN24.E3
  LAY6 w0.203: v1(15.45,24.2) 14.64,23.39 13.37,23.39 13.02,23.73 13.02,25.75 14.5,27.22 14.5,28.35 v1(14.47,28.38)
  LAY6 w0.305: v2(243.58,19.75) 242.87,19.04 242.87,15.53 237.19,9.85 153.28,9.85 150.86,12.26 147.26,12.26 144.87,9.87 127.44,9.87 126.18,11.13 118.1,11.13 116.78,9.81 97.99,9.81 95.77,12.03 91.83,12.03 89.59,9.79 61.5,9.79 58.15,13.14 47.92,13.14 46.58,14.48 46.58,26.37 38.14,34.81 22.02,34.81 v2(16.87,29.66) 15.59,28.38 v1(14.47,28.38) ; v1(15.45,24.2) 15.45,25.6 22.74,32.89 37.03,32.89 43.73,26.18 v1(44.38,25.54) 44.86,25.05 44.86,13.71 47.2,11.37 56.6,11.37 59.91,8.07 90.36,8.07 92.62,10.33 95.01,10.33 97.66,7.68 98.07,8.09 117.95,8.09 119.26,9.4 125.42,9.4 126.67,8.15 144.75,8.15 145.22,7.68 148,10.46 150.05,10.46 152.43,8.08 238.23,8.08 245.38,15.24 245.38,16.98 246.61,18.2 v2(246.61,19.17)
  LAY6 w0.406: v2(246.61,19.17) 245.44,20.34 244.17,20.34 v2(243.58,19.75)
  BOTTOM w0.203: U2526.28 137.75,80.44 v2(137.53,80.22) ; U29.4 237.75,39.48 v2(237.47,39.76) ; U23.3 v2(40.23,61.09) ; C458.1 v2(20.59,20.61) 21.08,20.61 C455.1 ; U16.4 15.53,19.96 v2(14.53,18.96) ; C50.2 C62.2 ; U18.3 v2(136.2,25.3) ; U22.91 45.49,68.26 v2(45.45,68.29) ; v2(60.76,59.89) 60.78,59.86 U22.27 ; C480.2 v2(43.15,61.47) ; v2(112.53,43.86) 112.53,43.87 C374.1 ; Q62.2 239.23,47.88 239.03,48.08 v2(238.58,48.08) ; 160.5,88.46 v2(160.7,88.26) ; v2(226.1,43.77) R48.1 ; R680.1 C316.2 v2(236.12,95.16) ; U2526.17 142.15,81.34 v2(142.25,81.44) ; R426.1 v2(43.2,62.41) ; v2(235.43,38.63) 235.43,38.39 235.64,38.17 U29.32 ; v2(54.23,70.62) 54.32,70.71 U22.113 ; C773.1 16.99,75.84 v2(16.98,75.83) ; U17.3 v2(19.31,26) ; v2(227.93,55.02) 229.05,53.9 v2(229.05,53.51) R720.1 ; U2526.3 v2(144.48,86.01) ; v2(24.44,90.66) C410.2 23.77,90.66 R341.1 ; v2(40.13,62.81) 40.13,62.81 C485.1 ; C457.1 v2(22.47,18.19) ; C490.1 v2(129.94,80.61) ; C487.2 v2(37.39,62.04) ; v2(47.79,61.67) 47.6,61.86 U22.75 ; Q61.2 v2(239.24,51.93) ; U29.30 235.3,37.37 v2(235.23,37.44) ; v2(207.93,62.36) 207.9,62.32 C70.2 ; v2(47.15,75.34) R421.2 ; v2(238.58,48.08) 238.31,47.81 Q21.2 ; v2(238.58,48.08) 238.58,48.63 R812.1 ; C70.2 C64.2 ; C70.2 C200.2 ; R423.2 v2(49.62,75.34) ; v2(226.7,48.28) R49.1 ; C2785.1 v2(70.26,99.62) ; CP52.2 165.44,97.6 ; 160.5,88.44 160.5,88.13 v2(160.3,87.93) ; v2(54.06,55.34) 53.92,55.48 U22.49 ; v2(57.83,70.52) 57.92,70.61 U22.122 ; v2(60.87,72.14) 61.15,72.42 61.15,73.48 60.97,73.66 v2(60.97,75.02) 61.46,75.02 R424.1 61.57,75 v2(62.51,75) C482.2 v2(66.47,75) 72.03,75 72.48,74.55 X4.2 X4.3 72.48,72.43 72.28,72.23 v2(71.68,72.23) v2(70.24,72.23) C484.2 62.47,72.23 62.39,72.15 v2(62.39,72.12) 62.36,72.12 62.17,71.93 62.17,71.5 61.77,71.11 v2(61.77,70.78) U22.1 ; v2(222.23,80.11) 223.22,81.09 R40.1 ; U9.24 128.32,43.4 v2(128.42,43.3) ; v2(220.42,83.99) 220.29,83.86 R39.1 ; v2(18.15,23.96) 18.07,23.87 C452.1 ; R414.2 64.07,59.83 v2(64.05,59.81) ; U2526.18 141.75,81.31 v2(141.64,81.42) ; R368.1 v2(191.92,12) ; U4.3 v2(242.32,44.05) ; C459.1 v2(16.87,29.66)
  BOTTOM w0.254: C178.2 201.93,63.14 v2(201.99,63.07) ; C218.1 199.63,72.68 C210.2 199.9,73.61 v2(199.77,73.74) 199.77,74.1 198.91,74.95 v2(198.79,74.95) ; C642.1 196.81,16.92 v2(196.12,16.92) ; v2(225.11,84.67) 224.67,84.23 C142.1 ; C76.2 207.11,70.49 v2(206.62,69.99) 206.2,70.41 C77.2 ; C53.2 210.43,70.34 v2(210.05,69.96) 209.6,70.41 C79.2 ; C180.2 201.44,62.27 v2(201.53,62.36) 201.63,62.26 C177.2 202.35,62.26 v2(202.45,62.36) 202.72,62.08 C176.2 ; C58.2 204.28,70.48 v2(204.72,70.04) 204.78,70.04 C78.2 ; C182.2 204.41,62.22 v2(204.28,62.36) 203.63,63 C190.2 ; C81.2 203.83,72.74 v2(203.36,72.27) 203.13,72.5 C209.2 ; C145.1 224.72,81.22 224.86,81.07 C112.2 224.86,79.95 v2(224.86,79.94) ; v2(206.1,62.36) 205.94,62.19 C63.2 ; v2(64.73,70.45) 64.73,70.12 R390.1 ; v2(207.93,60.15) 208,60.22 C191.2 ; C55.2 207.39,72.27 v2(207.02,72.27) 206.66,72.27 C56.2 ; v2(192.17,71.02) 192.17,71.04 R60.2 ; C75.2 207.92,70.39 v2(208.34,69.98) 208.81,70.45 C74.2 ; v2(222.93,69.93) 222.66,70.21 221.76,70.21 221.44,70.53 R43.2 221.57,70.84 221.57,71.72 R44.2 ; C483.2 v2(64.88,65.83) ; v2(209.76,60.15) 209.73,60.18 C181.2 ; C54.2 209.37,73.17 v2(208.85,73.68) 208.35,73.19 C80.2 ; v2(210.68,73.68) 210.18,73.19 C68.2 ; v2(205.19,72.27) 205.44,72.27 205.49,72.32 C57.2 ; R415.2 66.21,58.7 v2(66.2,58.71) ; v2(191.5,45.31) 191.85,45.66 R8.1
  BOTTOM w0.305: C702.1 v2(157.96,62.79) ; R46.2 v2(228.22,45.34) ; R547.2 234.99,42.37 C704.2 v2(234.99,41.82) ; U45.E1 179.25,94.97 U45.4 ; v2(21.81,25.07) 21.82,25.08 Q19.2 ; v2(131.68,42.67) 131.2,42.19 C387.2 ; v2(122.66,28.88) 122.67,28.88 X3.2 ; v2(122.66,28.88) 121.87,28.88 121.49,29.26 121.49,30.81 v2(121.48,30.82) 121.49,30.83 121.49,32.22 121.85,32.57 122.92,32.57 123.16,32.81 123.16,33.26 123.16,33.26 C371.2 ; v2(122.66,28.88) 125.62,28.88 125.95,29.21 v2(125.95,29.24) 125.95,31.5 v2(125.88,31.57) ; v2(21.86,66.59) 21.84,66.62 R778.1 ; C105.1 220.66,73.61 v2(220.73,73.68) ; R773.1 157.99,46.83 v2(157.99,46.83) ; C435.1 8.02,21.28 v1(7.85,21.45) C434.1 ; C213.2 203.01,69.7 v2(203,69.69) 203.02,69.68 C211.2 ; C114.2 219.02,68 v2(219,68.02) ; C656.1 200.27,17.28 199.9,16.91 v2(199.67,16.91) ; C2770.1 v2(147.28,80.9) ; C433.2 v2(6.28,24.04) ; R784.2 18.7,66.01 v2(18.69,66) ; v2(170.6,61.3) 170.51,61.39 C226.1 ; R232.1 C720.2 230.87,85.73 v2(230.42,85.73) ; R2986.1 R2987.1 136.88,77.72 v2(136.87,77.71) ; R219.2 232.31,86.59 R669.2 C308.1 231.79,87.33 v2(231.76,87.29) ; C317.1 240.46,94.93 240.76,94.93 v2(241.09,94.6) ; C710.2 47.15,92.88 v2(47.15,92.88) ; R682.1 241,95.45 v2(241.17,95.28) ; C148.1 C147.1 217.99,60.8 v2(217.99,60.8) ; C250.1 193.29,19.3 C416.1 192.29,19.3 191.99,19.59 191.99,20.25 v2(192.36,20.62) ; Q20.2 21.03,31.11 v2(21.54,31.63) ; C301.1 232.96,91.19 v2(232.97,91.18) ; C229.1 v2(169.81,64.11) ; v2(124.13,47.1) 123.82,47.42 R323.2 ; v2(237.5,84.39) 237.66,84.55 C716.1 238.13,84.34 240.59,81.88 C293.2 241.19,81.13 v2(241.18,81.12) ; C245.1 198.68,51 v2(198.89,51.21) ; C722.2 v2(238.19,97.44) ; R17.2 R26.2 195.72,50.94 v2(195,51.67) 194.9,51.76 C233.1 ; C436.2 7.63,15.6 v2(7.5,15.46) ; C774.2 17.48,65.95 v2(17.48,65.95) ; v2(182.04,63.97) 182.08,63.93 C220.1 ; v2(124.92,33.93) 125.16,33.93 C379.2 ; R234.1 242.21,81.97 v2(242.15,81.91) ; v2(194.62,15.17) 194.67,15.11 R435.2 ; v2(75.26,102.37) 75.26,102.37 C2782.2 ; R229.1 v2(236.36,100.93) ; v2(125.88,31.57) 125.88,32.23 125.58,32.53 124.66,32.53 124.35,32.84 C372.2 ; v2(125.88,31.57) X3.4 ; R2994.1 v2(139.98,77.7) ; C512.2 174.84,27.33 v1(174.52,27.66) ; C4.2 v2(178.47,42.94) C3.2 ; C104.1 v2(218.99,69.95) 219.01,69.93 C113.2 ; U10.3 136.59,46.29 v2(136.82,46.06) ; C179.2 204.79,61.58 C182.2 ; v2(202.9,53.98) 203.62,53.26 C185.2 ; C393.2 v2(119.64,41.79) ; C224.1 199.42,69.29 v2(199.18,69.53) ; R309.1 114.9,44.28 v2(114.75,44.43) ; C320.1 244.03,85.68 243.5,85.68 R673.1 v2(243.48,86.35) ; C146.1 220.77,60.83 v2(220.73,60.8) ; v2(120.13,36.68) 120.16,36.65 C381.2 120.9,37.44 C384.2 ; v2(217.99,73.68) 217.91,73.6 C103.1 ; R825.2 v2(156.56,44.6) ; C319.2 R233.1 C313.2 C312.2 v2(245.41,90.97) ; C417.1 216.11,14.89 v2(216.11,15.16) ; R235.1 241.76,86.08 v2(241.43,86.41) ; v2(210.32,95.27) 210.46,95.42 U50.4 ; C785.1 141.13,17.52 v2(141.12,17.51) ; C2784.2 79.19,99.29 C2790.2 C2787.2 v2(79.98,101.11) ; v2(151.19,14.21) 151.19,14.2 Q57.2 ; C397.2 v2(122.26,45.42) ; R80.2 195.63,71.15 v2(195.63,70.81) ; v2(244.7,85.43) 244.78,85.34 C315.1 ; v2(137.32,37.36) 137.41,37.45 C470.1 ; U8.2 117.69,46.41 v2(117.81,46.29) ; C2781.2 v2(76.25,103.31) ; C135.1 C127.1 222.25,68.14 v2(222.28,68.11) ; R310.1 133.99,42.69 v2(133.99,42.69) ; v2(213.42,60.8) 214.05,61.43 C149.1 ; R316.2 130.54,44.44 v2(130.93,44.82) ; v2(73.16,100.22) C2786.2 R802.1 ; R308.1 134.04,41.55 v2(134.04,41.55) ; U19.2 v2(137.43,35.16) ; v2(230.09,89.67) 230.32,89.67 230.87,89.12 C300.1 ; v2(175.05,96.05) 175.03,96.02 C321.2 ; C453.1 21.54,19.25 v2(21.56,19.27) ; C239.1 198.23,68.7 v2(198.23,68.22) ; C390.2 120.7,33.55 R307.1 120.62,34.15 v2(120.78,34.31) ; v2(31.54,76.03) 31.53,76.04 Q65.2 ; C700.1 159.88,62.6 v2(159.7,62.78) ; C305.1 v2(237.46,101.48) ; C392.2 v2(119.68,40.3) ; v2(130.39,86.76) R440.1 ; C219.1 199.34,70.3 v2(198.93,70.71) ; C391.2 119.71,38.81 v2(119.7,38.8) ; C2789.2 79.04,95.55 v2(79.04,96.43) 78.37,96.43 C2788.1 ; v2(201.1,17.51) 201.44,17.85 C643.1 ; v2(159.01,62.15) U59.5 ; R50.2 212.52,61.19 211.84,61.87 C201.1 211.59,62.35 v2(211.59,62.36) ; C214.2 200.58,69.7 v2(200.59,69.69) 200.58,69.68 C212.2 ; R3009.2 v2(72.32,102.33) ; U54.E1 160.5,88.44 161.2,87.74 U54.4 v2(162.03,87.74) ; C309.2 237.39,99.02 237.58,99.22 v2(237.7,99.22) ; v2(13.04,65.87) 13.14,65.97 R779.2 ; C2774.1 v2(147.42,84.8) ; v2(247.69,95.78) 247.69,96.01 247.27,96.43 C718.2 ; R463.1 v2(27.87,62.96) ; v2(216.16,73.68) 216.22,73.63 C134.1 ; v2(196.92,70.81) 196.77,70.95 C241.1 ; R378.2 v2(135.38,35.76) ; C781.2 25.98,70.04 v2(25.98,70.04) ; C314.2 v2(241.1,100.92) ; Q4.2 v2(18.7,64.53) ; C304.2 244.62,96.93 v2(244.63,96.93) ; v2(211.59,73.68) 211.63,73.65 C123.1 ; C388.2 127.79,45.4 v2(128.31,45.92) 128.64,46.24 C386.2 ; C431.1 v2(23.66,17.83) ; C377.2 131.13,43.79 v2(131.53,44.19) ; R785.2 v2(15.89,65.81) ; R47.2 v2(228.25,46.13) ; R789.1 v2(152.59,13.83) ; Q56.2 v2(149.19,18.3) ; v2(70.88,101.76) C2783.1 ; Q46.2 v2(27.23,63.57) ; C703.1 v2(233.93,44.87) ; R560.1 v2(48.72,94.15) ; R196.2 v2(126.45,27.61) ; C2765.1 v2(134.55,84.62) ; R821.1 v2(26.87,72.71) ; 190.13,45.26 190.41,44.97 v2(190.41,42.23) 190.09,41.91 v2(186.42,41.91) 186.16,42.18 186.16,44.44 v2(186.48,44.76) C6.2 186.98,46.3 187.81,47.12 188.98,47.12 189.7,46.4 v2(189.7,45.89) C5.2 190.13,45.26
  BOTTOM w0.406: C776.2 21.89,64.41 v2(21.89,64.31) ; C640.1 211,16.51 v2(211.64,16.51) ; R312.2 v2(134.83,38.79) ; C456.1 v2(21.55,13.51) ; C129.1 216.54,63.88 v2(216.98,64.32) 217.49,63.8 C128.1 ; v2(197.86,19.45) 198.42,19.45 C651.1 ; C696.1 v2(243.85,38.92) ; v2(208.88,20.06) 209.01,20.06 209.24,19.83 C652.1 ; C451.2 17.91,24.6 v2(17.9,24.59) ; C775.1 v2(15.18,75.78) ; C170.1 208.59,52.49 207.97,53.1 v2(207.97,54.16) ; v2(207.36,20.01) 206.79,20.01 C650.1 ; Q52.2 232.06,46.11 v2(231.86,46.31) ; C2769.1 147.51,82.21 v2(147.51,82.85) ; C653.1 203.69,20.03 v2(204.36,20.03) ; v2(205.7,53.55) 205.57,53.43 C172.1 ; Q45.2 28.17,59.35 27.93,59.58 v2(27.93,60) ; v2(196.36,20.03) 196.23,19.9 C644.1 ; v2(19.13,15.79) C454.1 ; C378.2 131.96,36.93 v2(131.96,36.93) ; C645.1 201.54,20.03 v2(200.86,20.03) ; C13.1 189.93,52.43 v2(189.45,52.91) ; C657.1 205.77,19.91 v2(205.82,19.96) ; v2(128.45,33.47) 128.18,33.2 C380.2 127.14,33.2 126.57,33.77 C389.2 ; C130.1 213.68,63.8 v2(213.17,64.32) 212.73,63.88 C131.1 ; R469.1 186.91,28.21 v2(187.04,28.08) ; C654.1 209.64,15.77 v2(209.64,15.78) ; C655.1 208.11,15.79 v2(208.54,15.79) ; v2(210.53,19.99) 211.19,19.99 C646.1 ; C698.1 v2(231.75,34.99) ; C383.1 v2(132.11,36.07) ; U21.1 v2(184.31,29.48) ; C296.2 v2(231.14,96.35) ; v2(27.59,70.42) C778.2
  BOTTOM w0.508: R3115.1 v2(98.44,87.39) ; R3115.1 R3116.1 R3117.1 v2(99.34,82.65) ; R3115.1 R3114.1 v2(98.3,89.18) ; CN35.12 v2(133.87,97.87) ; CN35.1 v2(144.87,97.87) ; C447.1 15.19,25.19 C449.1 15.2,24.45 v1(15.45,24.2) ; C244.1 195.81,52.76 196.42,53.37 196.42,53.75 v2(196.9,54.23) ; CN35.25 v2(129.87,101.23) ; v2(141.8,77.08) 142.04,77.33 C2767.2 ; CN35.20 v2(125.87,97.88) ; J5.E2 v2(89.82,85.68) ; v2(146.88,96.68) 146.87,96.69 CN35.E1 ; CN35.E2 v2(123.87,99.7) ; U25.2 128.28,85.4 128.71,84.97 v2(128.95,84.97) ; U12.2 v2(21.99,87.53) ; C325.2 158.74,79.77 v1(158.81,79.7) ; CN35.22 v2(126.87,101.23) ; C2766.2 v2(147.88,79.75) ; CN35.21 v2(125.87,101.17) ; CN35.34 v2(138.87,101.14) ; CN35.28 v2(132.87,101.04) ; v2(59.42,86.44) 58.76,86.44 CN7.2 ; C243.2 v2(174.88,68.31) ; C726.2 v1(41.31,92.02) ; R543.2 v2(243.99,37.71) ; CN35.7 v2(138.87,97.88) ; C641.1 205.21,16.95 v2(205.62,16.95) ; CN35.37 v2(141.87,101.04) ; CN35.4 v2(141.87,98.02) ; J5.E1 v2(97.42,88.52) ; v2(145.7,102.4) 145.7,102.4 CN35.40 ; CN35.31 v2(135.87,101.16) ; C2771.1 C2768.1 142.8,79.42 v2(142.53,79.69) ; C658.1 203.34,16.83 v2(203.45,16.94) ; U38.2 v2(48.71,89.56) ; CN35.19 v2(126.87,97.92)
  BOTTOM w0.762: v1(40.6,56.2) 40.46,56.34 C479.1 C477.1
  BOTTOM w1.016: C450.2 14.49,28.36 v1(14.47,28.38) 14.46,28.37 C448.2
  vias: v1(0.77,90.35) v1(0.77,87.81) v1(0.72,85.09) v1(0.78,82.47) v1(0.77,80.19) v1(0.77,77.65) v1(0.77,75.11) v1(0.77,72.57) v1(0.77,70.03) v1(0.77,67.49) v1(0.77,59.87) v1(0.77,57.33) v1(0.77,54.79) v1(0.77,52.25) v1(0.77,49.71) v1(0.77,47.17) v1(0.77,39.55) v1(0.77,37.01) v1(0.77,34.47) v1(0.77,31.93) v1(0.77,29.39) v1(0.77,26.85) v1(0.77,24.31) v1(0.78,20.93) v1(0.78,17.66) v1(0.72,13.34) v1(0.78,10.14) v1(0.8,64.34) v1(0.8,61.8) v1(0.87,7.4) v1(1.05,103.87) v1(1.04,101.33) v1(2.56,94.49) v1(3.05,7.43) v1(3.45,94.49) v1(3.42,90.22) v1(3.42,82.02) v1(3.42,76.56) v1(3.42,71.1) v1(3.5,36.79) v1(4.13,58.57) v1(4.37,65.4) v1(4.37,63.88) v1(4.3,61.17) v1(4.48,67.22) v1(4.81,32.41) v1(5.06,61.17) v1(5.01,54.46) v1(5.01,51.92) v1(5.01,49.38) v1(5.14,65.4) v1(5.14,63.88) v1(5.24,67.22) v1(5.59,7.43) v1(5.82,61.17) v1(5.9,65.4) v1(5.9,63.88) v1(6,67.22) v1(6.29,79.73) v1(6.29,78.95) v1(6.6,39.14) v1(6.83,34.31) v1(7.08,79.73) v1(7.08,78.95) v1(7.63,70.53) v1(8.11,85.58) v1(8.13,7.43) v1(8.25,50.68) v1(8.43,45.14) v1(8.86,30) v1(8.84,29.25) v1(9.3,82.88) v1(9.3,82.11) v1(9.3,81.35) v1(9.29,80.53) v1(9.29,79.76) v1(9.29,79) v1(10.47,90.79) v1(10.46,89.66) v1(10.41,52.62) v1(10.41,47.16) v1(10.41,41.7) v1(10.41,37.35) v1(10.67,7.43) v1(11.09,85.63) v1(13.21,7.43) v1(14.38,94.37) v1(15.27,94.37) v1(15.75,7.43) v1(16.26,58.45) v1(16.53,80.25) v1(16.53,79.46) v1(16.55,78.71) v1(16.62,59.43) v1(16.83,103.67) v1(16.81,101.13) v1(17.06,83.47) v1(17.06,82.71) v1(17.06,81.95) v1(17.02,58.45) v1(17.38,59.43) v1(17.79,58.45) v1(18.14,59.43) v1(19.97,83.42) v1(19.97,82.66) v1(19.97,81.9) v1(19.97,81.14) v1(20.58,56.79) v1(20.58,56.03) v1(20.58,55.27) v1(21.05,94.32) v1(21.61,94.78) v1(23.37,95.21) v1(23.37,94.45) v1(24.26,95.21) v1(24.26,94.45) v1(24.86,55.93) v1(24.86,55.16) v1(24.86,54.4) v1(25.36,104.5) v1(25.81,80.63) v1(26.19,102.59) v1(26.7,80.6) v1(28.12,104.52) v1(28.12,102.74) v1(28.25,81.77) v1(30.94,62.42) v1(30.94,61.51) v1(31.15,66.09) v1(31.15,64.82) v1(31.56,61.97) v1(31.91,66.09) v1(31.91,64.82) v1(33.36,68.8) v1(33.43,70.51) v1(33.42,69.69) v1(34.21,70.52) v1(34.18,69.69) v1(34.21,68.78) v1(34.31,74.21) v1(34.31,73.45) v1(34.61,77.2) v1(34.61,76.3) v1(34.94,69.69) v1(35.07,74.15) v1(34.99,70.49) v1(35.08,73.4) v1(35.27,79.47) v1(35.37,77.2) v1(35.37,76.3) v1(36.04,79.47) v1(36.1,78.43) v1(36.14,77.2) v1(36.14,76.3) v1(36.8,79.47) v1(36.86,78.43) v1(36.9,77.2) v1(37.55,87.57) v1(39.16,20.72) v1(39.08,15.96) v1(39.27,27.11) v1(39.91,15.98) v1(43.57,104.67) v1(43.62,102.74) v1(45.96,97.85) v1(46.11,104.67) v1(46.33,10.62) v1(46.38,9.88) v1(46.74,97.85) v1(47.25,9.76) v1(48.05,101.39) v1(48.18,9.79) v1(48.65,104.67) v1(49.45,98.97) v1(50.15,10.61) v1(50.38,85.7) v1(50.94,10.59) v1(51.11,85.7) v1(51.19,104.67) v1(51.94,96.75) v1(52.23,101.24) v1(53.5,7.49) v1(53.73,104.67) v1(54.78,98.61) v1(56.08,101.36) v1(56.22,39.92) v1(57.75,33.51) v1(58.81,104.67) v1(59.07,98.04) v1(61.24,7.4) v1(61.35,104.67) v1(61.68,99.89) v1(63.66,7.49) v1(63.77,12.72) v1(63.87,10.71) v1(63.89,104.67) v1(64.12,97.96) v1(65.48,17.83) v1(65.76,12.61) v1(65.76,11.75) v1(66.2,7.49) v1(66.43,104.67) v1(68.74,7.49) v1(68.97,104.67) v1(71.28,7.49) v1(71.48,12.18) v1(71.51,104.67) v1(73.82,7.49) v1(73.96,57.02) v1(74.05,104.67) v1(74.89,23.99) v1(74.89,23.23) v1(75.46,35.57) v1(75.78,23.99) v1(75.78,23.23) v1(76.36,7.49) v1(76.59,104.67) v1(78.14,22.36) v1(78.14,21.43) v1(78.14,20.52) v1(79.13,104.67) v1(79.29,7.47) v1(81.67,104.67) v1(81.83,7.47) v1(82.66,47.68) v1(83.58,101.42) v1(84.37,7.47) v1(86.02,104.65) v1(86.91,7.47) v1(89.45,7.47) v1(89.65,104.73) v1(90.08,101.36) v1(91.22,7.46) v1(92.84,104.6) v1(93.71,58.02) v1(93.88,98.45) v1(94.51,58.02) v1(94.77,98.45) v1(95.14,7.44) v1(95.19,55.47) v1(95.57,104.64) v1(96.59,101.58) v1(97.07,7.47) v1(97.65,104.66) v1(99.61,7.47) v1(100.15,97.22) v1(100.27,104.66) v1(100.2,100.94) v1(100.37,102.8) v1(101.04,97.22) v1(101.52,98.31) v1(102.15,7.47) v1(102.41,98.31) v1(103.35,22.02) v1(103.35,21.26) v1(104.24,22.02) v1(104.24,21.26) v1(107.23,7.47) v1(107.34,104.67) v1(108.48,27.05) v1(108.48,26.29) v1(109.12,18.81) v1(109.24,27.05) v1(109.24,26.29) v1(109.28,97.41) v1(109.28,96.52) v1(109.53,7.4) v1(109.88,104.67) v1(110,27.05) v1(110,26.29) v1(110.77,26.29) v1(111.18,49.59) v1(111.53,26.29) v1(111.92,7.4) v1(112.15,104.67) v1(112.35,17.96) v1(113.3,50.25) v1(113.42,97.13) v1(114.23,90.63) v1(114.3,86.81) v1(114.58,13.71) v1(114.69,104.67) v1(114.85,7.47) v1(115.12,90.63) v1(115.19,86.81) v1(116.37,101.45) v1(116.37,100.69) v1(117.23,104.67) v1(117.26,101.45) v1(117.26,100.69) v1(118.34,97.1) v1(119.07,102.23) v1(119.77,104.67) v1(121.13,101.34) v1(121.73,92.01) v1(122.15,97.81) v1(122.18,85.75) v1(122.19,17.75) v1(122.19,16.98) v1(122.19,16.22) v1(122.19,15.46) v1(122.31,104.67) v1(122.44,87.02) v1(122.62,92.01) v1(123.17,103.04) v1(123.99,88.61) v1(124.02,87.04) v1(124.22,84.45) v1(124.31,85.33) v1(124.85,104.67) v1(124.88,88.61) v1(125.55,17.63) v1(126.31,17.63) v1(127.07,17.63) v1(127.39,104.67) v1(127.55,7.47) v1(127.84,17.63) v1(129.93,104.67) v1(132.47,104.67) v1(135.01,104.67) v1(135.06,16.21) v1(135.17,7.47) v1(135.82,16.21) v1(136.65,16.22) v1(137.41,16.22) v1(137.55,104.67) v1(137.71,7.47) v1(138.2,16.21) v1(139,17.41) v1(139.09,16.21) v1(139.48,104.63) v1(140.25,7.47) v1(141.22,27.58) v1(141.22,26.81) v1(141.22,26.03) v1(141.22,25.26) v1(141.97,27.58) v1(141.97,26.81) v1(141.97,26.03) v1(141.97,25.26) v1(142.02,104.63) v1(142.79,7.47) v1(144.56,104.63) v1(144.7,7.5) v1(146.36,59.23) v1(146.74,7.48) v1(147.03,104.43) v1(149.57,104.43) v1(149.94,52.94) v1(150.84,47.04) v1(150.86,46.13) v1(152.32,7.5) v1(152.47,104.49) v1(154.86,7.5) v1(155.01,104.49) v1(156.22,46.71) v1(156.22,45.97) v1(157.4,7.5) v1(157.55,104.49) v1(158.05,79.7) v1(158.63,59.04) v1(158.63,58.25) v1(159.94,7.5) v1(160.09,104.49) v1(160.7,62.29) v1(161.05,81.08) v1(161.14,62.89) v1(161.81,81.08) v1(162.48,7.5) v1(162.63,104.49) v1(162.97,83.04) v1(163.14,76.51) v1(163.13,75.57) v1(163.15,71.51) v1(163.99,83.04) v1(164.04,76.5) v1(164.04,75.56) v1(164.27,51.95) v1(164.43,84.43) v1(164.64,71.43) v1(165,83.04) v1(165.02,7.5) v1(165.17,104.49) v1(165.09,51.94) v1(165.09,51.06) v1(165.09,50.27) v1(165.45,84.43) v1(165.43,71.43) v1(166.55,98.71) v1(167.29,98.7) v1(167.39,57.09) v1(167.39,56.36) v1(167.56,7.5) v1(167.71,104.49) v1(168.17,57.08) v1(168.18,56.35) v1(169.03,88.07) v1(168.99,86.97) v1(169.84,88.07) v1(169.81,86.96) v1(170.1,7.5) v1(170.25,104.49) v1(172.13,95.43) v1(172.64,7.5) v1(172.79,104.49) v1(172.88,95.42) v1(173.63,95.43) v1(174.65,70.6) v1(175.11,7.5) v1(175.33,104.49) v1(177.65,7.5) v1(177.88,10.22) v1(180.19,7.5) v1(181.45,90.1) v1(182.21,90.1) v1(182.38,23.91) v1(182.73,7.5) v1(183,90.12) v1(183.07,24.29) v1(183.72,95.14) v1(183.76,90.12) v1(184.08,95.79) v1(184.46,95.13) v1(184.65,90.25) v1(184.67,89.45) v1(184.82,95.77) v1(185.21,95.14) v1(185.27,7.5) v1(185.35,96.45) v1(185.47,90.25) v1(185.54,89.42) v1(185.96,95.15) v1(186.49,95.84) v1(186.62,96.54) v1(186.68,95.12) v1(187.2,95.8) v1(187.39,95.11) v1(187.81,7.5) v1(188.11,90.19) v1(188.11,89.44) v1(188.11,88.67) v1(188.85,88.69) v1(189.61,88.69) v1(190.35,7.5) v1(192.89,7.5) v1(194.04,90) v1(194.04,89.11) v1(194.03,88.29) v1(194.35,7.47) v1(195.12,7.47) v1(195.88,7.47) v1(196.64,7.47) v1(200.51,7.5) v1(203.05,7.5) v1(204.83,94.06) v1(204.89,88.94) v1(205.37,88.43) v1(205.42,97.11) v1(205.52,94.09) v1(205.52,93.36) v1(205.59,7.5) v1(205.92,87.95) v1(206.16,97.11) v1(206.9,97.11) v1(207.26,91.8) v1(207.21,88.47) v1(208.04,104.68) v1(208.01,91.8) v1(208.13,7.5) v1(208.93,91.52) v1(208.89,90.58) v1(209.26,104.81) v1(209.2,88.86) v1(209.65,91.52) v1(210.12,90.61) v1(210.13,88.87) v1(210.67,7.5) v1(210.85,88.89) v1(211.38,90.61) v1(211.56,88.88) v1(211.87,93.58) v1(212.27,88.95) v1(212.62,93.58) v1(212.69,90.55) v1(212.81,88.41) v1(213.21,7.5) v1(213.36,93.58) v1(213.46,90.55) v1(214.08,93.58) v1(214.24,90.55) v1(215.75,7.5) v1(216.81,103.44) v1(216.81,102.67) v1(217.56,93.54) v1(218.2,104.68) v1(218.33,93.52) v1(218.29,7.5) v1(220.74,104.68) v1(220.83,7.5) v1(223.28,104.68) v1(223.37,7.5) v1(225.6,7.47) v1(225.82,104.68) v1(227.35,104.55) v1(228.14,7.47) v1(229.89,104.55) v1(230.57,33.4) v1(230.68,7.47) v1(231.26,39.15) v1(231.27,38.38) v1(231.26,32.79) v1(232.43,104.55) v1(233.22,7.47) v1(234.09,65.95) v1(234.97,104.55) v1(235.76,7.47) v1(237.51,104.55) v1(238.3,7.47) v1(240.05,104.55) v1(240.01,7.51) v1(240.43,69.46) v1(240.42,67.85) v1(241.32,36.65) v1(241.33,35.87) v1(241.33,35.11) v1(242.08,36.65) v1(242.09,35.87) v1(242.09,35.11) v1(242.19,31.49) v1(242.21,30.72) v1(242.21,29.95) v1(242.59,104.55) v1(242.84,36.65) v1(242.85,35.87) v1(242.85,35.11) v1(243.17,56.94) v1(243.18,56.17) v1(243.18,55.41) v1(243.38,7.47) v1(243.44,88.46) v1(244.39,56.93) v1(244.4,56.16) v1(244.4,55.39) v1(245.13,104.55) v1(245.46,87.46) v1(245.98,102.14) v1(246.22,87.46) v1(246.49,7.4) v1(246.98,87.46) v1(247.26,101.72) v1(247.27,101) v1(247.24,98.43) v1(247.32,100.26) v1(247.67,104.55) v1(247.71,94.78) v1(247.71,94.01) v1(247.71,93.25) v1(247.71,92.49) v1(247.71,91.73) v1(247.71,90.97) v1(247.71,89.44) v1(247.71,88.68) v1(247.71,87.92) v1(248.16,60.16) v1(248.14,56.89) v1(248.15,56.12) v1(248.15,55.35) v1(248.2,100.4) v1(248.19,80.21) v1(248.19,77.48) v1(248.19,74.75) v1(248.19,72.02) v1(248.19,69.29) v1(248.19,66.56) v1(248.19,63.83) v1(248.78,99.82) v1(249.98,7.4) v1(250.21,104.55) v1(251.44,94.85) v1(252.42,104.59) v1(252.44,101.47) v1(252.44,98.93) v1(252.44,96.39) v1(252.44,93.85) v1(252.44,91.31) v1(252.44,88.77) v1(252.44,86.23) v1(252.44,83.69) v1(252.44,81.15) v1(252.44,78.61) v1(252.44,76.07) v1(252.44,73.53) v1(252.44,70.99) v1(252.44,68.45) v1(252.44,65.91) v1(252.44,63.37) v1(252.44,60.83) v1(252.44,58.29) v1(252.44,55.75) v1(252.44,53.21) v1(252.44,50.67) v1(252.44,48.13) v1(252.44,45.59) v1(252.44,43.05) v1(252.44,40.51) v1(252.44,37.97) v1(252.44,35.43) v1(252.44,32.89) v1(252.44,30.35) v1(252.44,27.81) v1(252.44,25.27) v1(252.44,22.73) v1(252.44,20.19) v1(252.44,17.65) v1(252.44,15.11) v1(252.44,12.57) v1(252.44,10.03) v1(252.44,7.49) v2(1.23,45.12) v2(1.36,42.6) v2(2.19,13.33) v2(2.27,11.96) v2(2.3,12.58) v2(2.43,19.56) v2(2.46,18.99) v2(3.26,46.42) v2(3.24,41.49) v2(4.82,88) v2(5.34,45.1) v2(5.36,42.58) v2(5.78,25.95) v2(6.5,25.95) v2(6.9,87.97) v2(7.93,87.31) v2(9.97,87.3) v2(9.91,83.23) v2(10.44,83.23) v2(11.19,79.88) v2(13.26,20.23) v2(13.26,18.96) v2(13.26,17.69) v2(13.9,79.65) v2(14.53,20.23) v2(14.53,17.69) v2(15.34,70.77) v2(15.39,71.99) v2(15.8,20.23) v2(15.8,18.96) v2(15.8,17.69) v2(16.29,72) v2(16.34,70.77) v2(17.23,7.23) v2(18.05,84.86) v2(19.77,7.23) v2(20.12,92.21) v2(20.16,90.83) v2(20.33,101.57) v2(21.28,103.33) v2(21.27,99.83) v2(22.31,7.23) v2(23.41,103.33) v2(23.41,99.85) v2(24.56,101.56) v2(24.55,80.49) v2(24.85,7.23) v2(27.39,7.23) v2(29.6,88.95) v2(29.93,7.23) v2(31.41,88.49) v2(32.47,7.23) v2(34.75,88.01) v2(35.01,7.23) v2(35.86,92.28) v2(36.9,88.01) v2(37.31,89.8) v2(37.55,7.23) v2(39.08,7.23) v2(40.09,7.23) v2(40.36,12.12) v2(41.31,13.88) v2(41.3,10.39) v2(42.63,7.23) v2(43.44,13.88) v2(43.44,10.4) v2(44.3,91.92) v2(44.59,12.11) v2(45.06,91.94) v2(45.17,7.23) v2(47.22,14.64) v2(47.71,7.23) v2(48.48,37.27) v2(48.94,15.08) v2(50.25,7.23) v2(52.79,7.23) v2(54.71,97.68) v2(58.85,31.99) v2(60.28,31.81) v2(71.62,67.41) v2(71.87,90.22) v2(73.26,97.93) v2(73.26,97.16) v2(73.26,96.4) v2(73.34,32.59) v2(74.02,97.93) v2(74.02,97.16) v2(74.02,96.4) v2(74.78,97.93) v2(74.78,97.16) v2(74.78,96.4) v2(74.98,29.56) v2(75.35,91.69) v2(75.7,12.47) v2(75.93,31.32) v2(75.92,27.82) v2(76.78,56.27) v2(78.02,67.05) v2(78.06,31.32) v2(78.06,27.84) v2(78.18,98.21) v2(78.18,97.13) v2(78.25,12.24) v2(79.21,29.55) v2(80.37,91.61) v2(80.31,70.05) v2(81.97,69.49) v2(82.7,35.44) v2(84.06,97.29) v2(84.33,44.74) v2(84.58,96.77) v2(85.29,56.27) v2(86.05,70.42) v2(88.63,47.96) v2(88.63,47.37) v2(89.39,46.12) v2(90.91,41.93) v2(90.94,40.47) v2(90.9,38.97) v2(91.45,51.33) v2(91.42,49.55) v2(91.51,46.59) v2(91.81,48.32) v2(93.32,49.79) v2(93.31,48.01) v2(94.76,52.57) v2(94.87,51.38) v2(98.34,77.08) v2(98.43,62.29) v2(98.56,65.02) v2(98.74,61.11) v2(98.98,78.37) v2(99.56,18.65) v2(99.56,15.9) v2(99.79,65.85) v2(102.36,102.51) v2(102.52,10.67) v2(103.31,104.27) v2(103.3,100.77) v2(103.85,14.01) v2(104.8,15.78) v2(104.79,12.28) v2(105.2,89.26) v2(105.44,104.27) v2(105.44,100.79) v2(105.71,89.28) v2(106.41,7.36) v2(106.59,102.5) v2(106.92,15.78) v2(106.93,12.29) v2(107.41,81.35) v2(107.4,80.32) v2(108.07,14.01) v2(108.49,22.75) v2(109.07,42.15) v2(109.07,40.66) v2(109.07,39.16) v2(109.07,37.66) v2(109.07,36.17) v2(109.07,34.68) v2(109.07,33.18) v2(109.07,31.68) v2(109.03,29.43) v2(109.1,21.6) v2(112.17,77.21) v2(112.82,77.21) v2(113.22,68.24) v2(113.82,24.34) v2(113.94,22.73) v2(116.05,36.43) v2(116.03,33.45) v2(116.03,31.62) v2(116.1,34.58) v2(116.2,39.33) v2(116.22,37.6) v2(116.48,40.71) v2(116.52,42.01) v2(117.48,7.3) v2(118.89,49.92) v2(119.42,49.92) v2(123.54,79.74) v2(124.53,41.77) v2(124.67,40.51) v2(124.63,39.28) v2(125.65,16.86) v2(125.8,41.77) v2(125.8,40.5) v2(125.8,39.23) v2(126.28,16.86) v2(126.87,7.3) v2(126.92,16.86) v2(127.01,49.7) v2(127.07,41.77) v2(127.07,40.5) v2(127.07,39.23) v2(127.27,14.41) v2(127.31,13.83) v2(127.45,100.57) v2(127.55,16.86) v2(127.49,11.02) v2(127.93,29.24) v2(127.93,28.58) v2(128.21,73.24) v2(128.19,16.86) v2(128.34,49.67) v2(128.5,72.32) v2(128.52,71.65) v2(128.71,10.52) v2(128.72,10.02) v2(129.29,100.58) v2(129.74,49.69) v2(129.93,73.36) v2(130.35,7.31) v2(130.45,100.57) v2(130.52,29.28) v2(130.52,28.62) v2(130.99,81.68) v2(131.02,81.21) v2(131.03,73.87) v2(131.36,49.11) v2(132.29,100.59) v2(132.49,73.52) v2(132.72,7.31) v2(133.16,72.97) v2(133.16,71.88) v2(133.48,100.55) v2(135.06,90.61) v2(135.27,100.59) v2(135.37,30.63) v2(135.93,30.63) v2(136.2,68.25) v2(136.42,91.31) v2(137.48,68.28) v2(137.53,29.95) v2(137.84,91.33) v2(138.09,29.95) v2(138.83,68.27) v2(139.08,91.44) v2(139.11,85.5) v2(139.11,84.23) v2(139.11,82.96) v2(140.19,37.4) v2(140.38,85.5) v2(140.38,84.23) v2(140.38,82.96) v2(140.78,37.42) v2(141.65,85.5) v2(141.65,84.23) v2(141.65,82.96) v2(144.33,51.41) v2(148.18,85.26) v2(148.48,88.32) v2(148.56,87.23) v2(149.19,86.57) v2(149.45,85.38) v2(149.46,83.85) v2(150.61,52.95) v2(153.61,49.79) v2(153.9,48.93) v2(154.56,49.64) v2(154.93,48.97) v2(155.52,49.84) v2(158.01,61.26) v2(158.01,60.73) v2(158.01,60.19) v2(159.33,44.75) v2(160.2,42.71) v2(160.56,53.39) v2(162.37,92.39) v2(162.32,83.32) v2(162.29,82.83) v2(162.62,46.04) v2(162.63,45.37) v2(162.59,44.67) v2(163.56,44.65) v2(163.58,46.03) v2(163.59,45.36) v2(165.93,77.92) v2(165.98,79) v2(167.86,23.9) v2(168.6,60.6) v2(168.64,23.15) v2(168.94,84.56) v2(169.06,60.61) v2(169.17,23.16) v2(169.56,84.51) v2(169.52,60.6) v2(170.35,82.96) v2(170.29,36.64) v2(170.57,83.39) v2(170.62,60.8) v2(170.6,60.31) v2(171.38,61.17) v2(171.53,95.63) v2(171.52,36.58) v2(171.93,49.23) v2(172.5,94.93) v2(172.5,49.23) v2(172.67,27.2) v2(172.94,81.92) v2(172.96,81.37) v2(173.08,103.46) v2(173.23,94.93) v2(173.59,103.46) v2(173.63,15.74) v2(173.83,12.41) v2(174,94.94) v2(174.01,40.83) v2(174.1,103.46) v2(174.11,70.83) v2(174.12,70.34) v2(174.58,46.17) v2(174.6,103.46) v2(174.66,77.55) v2(174.8,20.04) v2(175.11,103.46) v2(175.11,16.92) v2(175.36,18.86) v2(175.7,103.46) v2(175.71,95.98) v2(176,56.51) v2(176.21,103.46) v2(176.34,104.95) v2(176.65,70.02) v2(176.66,58.21) v2(176.71,97.39) v2(176.87,18.86) v2(176.89,54.69) v2(177.55,63.97) v2(178.32,95.6) v2(178.36,18.86) v2(178.61,95.98) v2(178.71,58.87) v2(178.88,104.95) v2(179.24,85.21) v2(179.46,63.97) v2(179.76,70.03) v2(180.27,57.91) v2(180.36,18.86) v2(180.51,45.32) v2(180.6,56.22) v2(180.61,16.92) v2(180.96,61.72) v2(180.98,45.3) v2(181.42,104.95) v2(181.45,45.3) v2(181.75,85.21) v2(181.82,102.48) v2(181.87,18.86) v2(182.23,85.21) v2(182.61,16.92) v2(182.61,16.34) v2(182.71,85.2) v2(183.37,20.03) v2(183.37,19.45) v2(183.37,18.86) v2(183.96,104.95) v2(183.96,60) v2(184.61,60) v2(184.76,85.19) v2(184.81,52.58) v2(184.87,18.86) v2(185.26,52.58) v2(185.43,95.81) v2(185.61,16.92) v2(185.74,52.59) v2(185.89,95.83) v2(186.12,49.55) v2(186.5,104.95) v2(187.11,16.92) v2(187.86,19.45) v2(187.86,18.86) v2(189.04,104.95) v2(189.21,95.46) v2(189.63,66.88) v2(190.27,66.88) v2(190.56,73.05) v2(190.56,72.41) v2(190.56,60.18) v2(190.86,18.86) v2(190.9,71.02) v2(190.92,69.01) v2(191.11,16.92) v2(191.54,66.88) v2(191.58,104.95) v2(192.17,66.88) v2(192.39,74.95) v2(192.39,74.32) v2(192.39,73.05) v2(192.39,72.41) v2(192.62,16.92) v2(192.62,16.34) v2(192.81,66.88) v2(192.81,65.81) v2(194.12,104.95) v2(194.1,47.94) v2(194.22,58.23) v2(194.86,19.45) v2(195.12,85.54) v2(196.4,19.09) v2(196.55,84.64) v2(196.66,104.95) v2(196.7,12.07) v2(198.95,48.98) v2(198.95,47.03) v2(199.2,104.95) v2(199.36,19.45) v2(200.85,81.45) v2(200.93,51.58) v2(200.93,49.63) v2(200.93,48.31) v2(200.93,46.33) v2(200.93,18.87) v2(201.07,16.32) v2(201.74,104.95) v2(202.26,84.76) v2(202.26,84.27) v2(202.26,83.77) v2(202.26,83.32) v2(202.26,82.86) v2(202.53,50.93) v2(202.53,48.98) v2(202.53,47.04) v2(203.11,81.09) v2(203.28,63.87) v2(203.78,17.99) v2(204.28,104.95) v2(204.36,18.28) v2(204.41,48.98) v2(204.41,47.03) v2(204.71,95.6) v2(204.95,93.45) v2(205.17,95.6) v2(205.63,95.6) v2(205.63,64.65) v2(205.88,67.3) v2(205.88,66.6) v2(206.05,93.63) v2(206.13,95.6) v2(206.19,51.58) v2(206.19,49.63) v2(206.19,47.68) v2(206.19,45.5) v2(206.19,44.85) v2(206.53,93.63) v2(206.67,91.78) v2(206.82,104.95) v2(207.13,15.73) v2(207.47,64.65) v2(207.97,50.93) v2(207.97,48.98) v2(207.97,46.92) v2(208.37,93.63) v2(208.82,98.55) v2(208.83,93.63) v2(209.02,67.29) v2(209.03,66.58) v2(209.03,65.93) v2(209.32,93.63) v2(209.29,64.65) v2(209.51,97.11) v2(209.53,96.59) v2(210.44,51.67) v2(210.42,47.55) v2(210.42,46.25) v2(210.42,45.6) v2(210.42,44.95) v2(210.76,90.54) v2(210.78,84.74) v2(211.14,104.94) v2(211.22,91.25) v2(211.24,84.73) v2(211.59,74.95) v2(211.59,74.32) v2(211.85,91.25) v2(211.8,84.74) v2(211.85,19.93) v2(211.96,90.47) v2(212,49.38) v2(212,47.42) v2(212.26,84.73) v2(212.49,91.25) v2(212.62,82.74) v2(212.62,80.78) v2(212.62,78.83) v2(212.81,84.74) v2(212.97,88.99) v2(213.12,91.25) v2(213.12,16.35) v2(213.75,104.88) v2(213.76,91.25) v2(213.8,69.9) v2(214.17,103.61) v2(214.39,91.25) v2(214.39,84.73) v2(214.67,52.48) v2(214.66,50.6) v2(214.66,48.64) v2(214.66,46.69) v2(214.78,103.63) v2(214.89,19.34) v2(215.32,93.7) v2(215.46,103.6) v2(215.61,104.85) v2(215.71,69.9) v2(216.11,103.48) v2(216.16,74.33) v2(216.72,47.51) v2(217.08,59.51) v2(217.29,100.41) v2(217.48,69.9) v2(217.86,50.83) v2(217.93,47.51) v2(217.99,60.15) v2(218.36,43.94) v2(218.91,58.88) v2(218.91,57.61) v2(219.14,16.33) v2(219.77,49.72) v2(219.82,50.8) v2(220.03,47.77) v2(220.03,45.82) v2(220.42,82.06) v2(222.25,83.43) v2(222.7,93.24) v2(224.44,85.21) v2(224.61,16.33) v2(225.97,90.16) v2(225.97,89.19) v2(225.99,88.19) v2(227.61,16.33) v2(228.62,79.9) v2(229.11,16.92) v2(229.59,63.11) v2(229.87,81.54) v2(229.88,71.61) v2(230.24,66.56) v2(230.23,66) v2(230.28,64.2) v2(231.55,63.11) v2(232.23,64.2) v2(232.2,61.14) v2(233.5,63.11) v2(233.57,54.9) v2(233.69,89.77) v2(233.95,83.31) v2(233.96,58.58) v2(234.08,66.58) v2(234.15,61.14) v2(234.22,71.62) v2(234.25,63.08) v2(234.42,95.13) v2(235.25,78.66) v2(235.18,54.3) v2(235.86,18.86) v2(236.03,58.8) v2(236.46,90.34) v2(236.4,58.54) v2(236.58,54.77) v2(236.75,61.14) v2(236.87,78.13) v2(236.89,89.12) v2(236.89,88.54) v2(236.88,37.86) v2(236.88,37.36) v2(237,90.36) v2(237.18,57.72) v2(237.34,66.67) v2(237.39,37.86) v2(237.39,37.36) v2(237.74,87.64) v2(238.08,88.1) v2(238,53.89) v2(238.3,66.58) v2(238.37,54.28) v2(238.45,88.5) v2(238.87,87.36) v2(239.2,87.87) v2(239.25,66.74) v2(239.51,88.35) v2(239.88,71.66) v2(239.92,69.06) v2(241.5,97.6) v2(241.67,91.91) v2(248.57,97.43) v2(248.93,97.06)
